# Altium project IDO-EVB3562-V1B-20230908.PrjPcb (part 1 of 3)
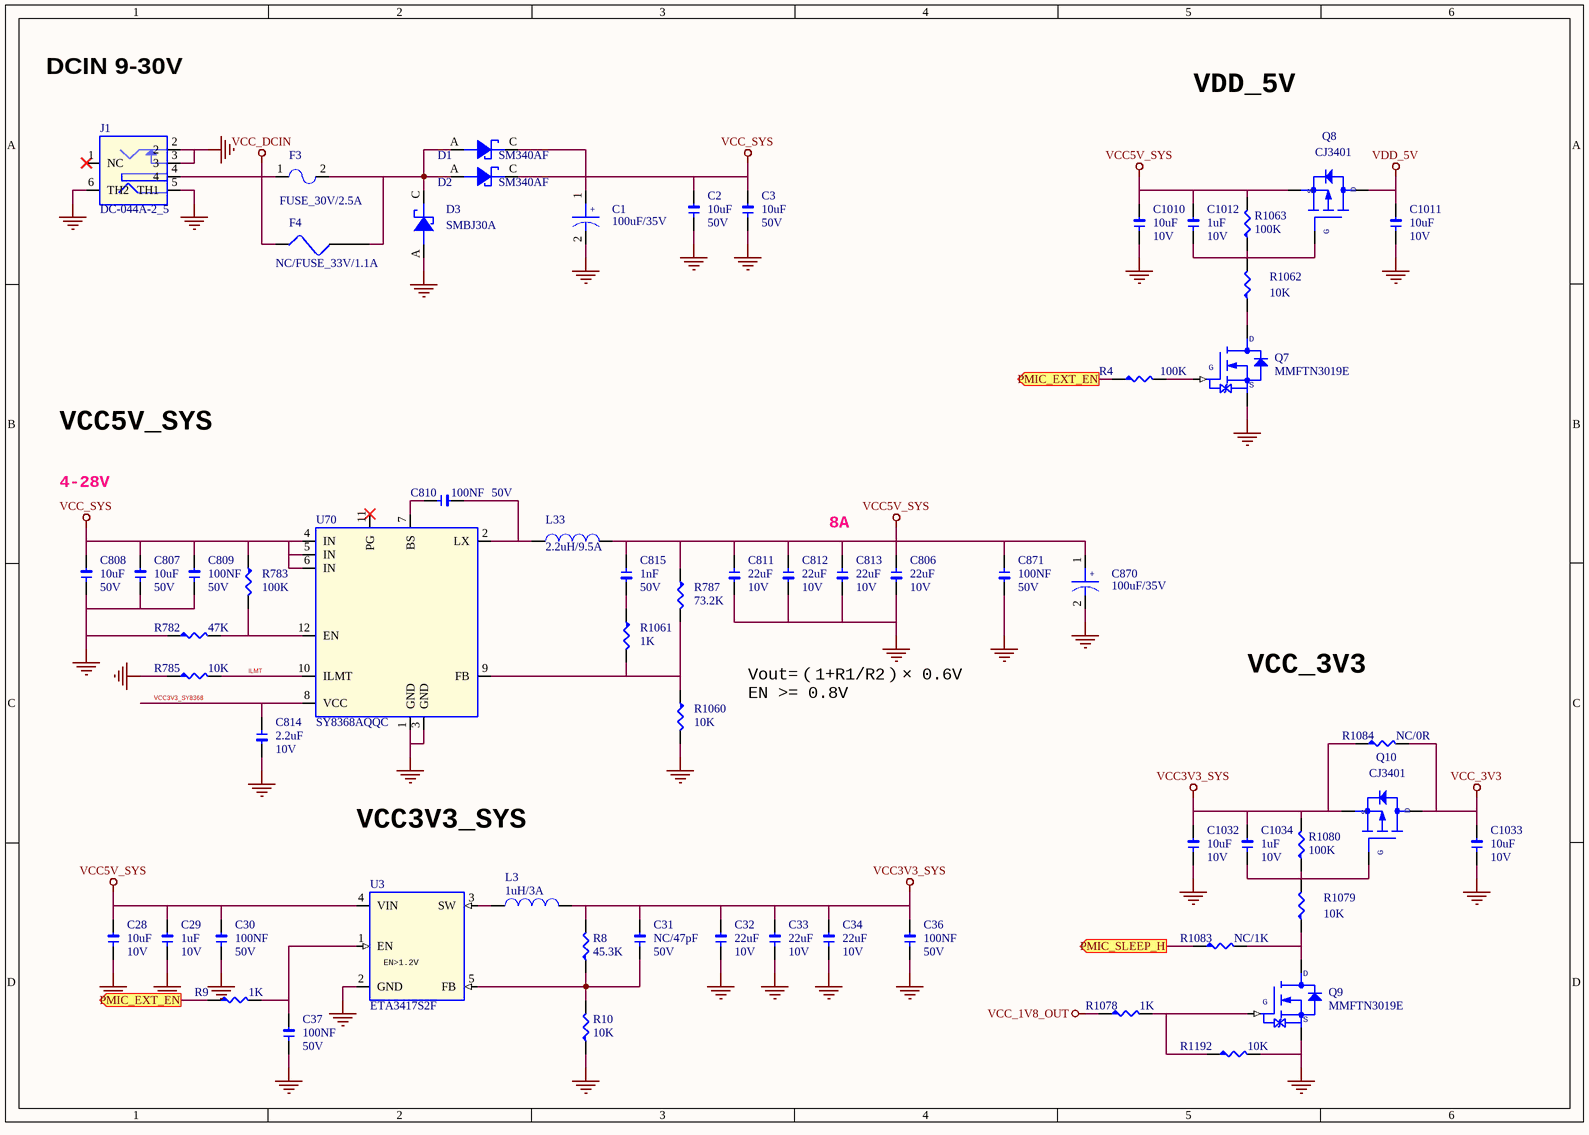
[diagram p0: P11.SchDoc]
14 sheets, 758 parts. Net scope: flat (ports and power ports of the same name join across sheets).
Sheets:
  P11.SchDoc
  P12.SchDoc
  P13.SchDoc
  P14.SchDoc
  P15.SchDoc
  P16.SchDoc
  P17.SchDoc
  P18.SchDoc
  P19.SchDoc
  P20.SchDoc
  P21. USB3.SchDoc
  P22.SchDoc
  P24.SchDoc
  P30.SchDoc

## Sheet P11.SchDoc
size 297 x 209 mm

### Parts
C1  100uF/35V  [CAPAE660X770]
C2  10uF  DSC2: 50V  [1206]
C3  10uF  DSC2: 50V  [1206]
C28  10uF  DSC2: 10V  [1206]
C29  1uF  DSC2: 10V  [1206]
C30  100NF  DSC2: 50V  [1206]
C31  NC/47pF  DSC2: 50V  [1206]
C32  22uF  DSC2: 10V  [1206]
C33  22uF  DSC2: 10V  [1206]
C34  22uF  DSC2: 10V  [1206]
C36  100NF  DSC2: 50V  [1206]
C37  100NF  DSC2: 50V  [1206]
C806  22uF  DSC2: 10V  [1206]
C807  10uF  DSC2: 50V  [1206]
C808  10uF  DSC2: 50V  [1206]
C809  100NF  DSC2: 50V  [1206]
C810  100NF  DSC2: 50V  [1206]
C811  22uF  DSC2: 10V  [1206]
C812  22uF  DSC2: 10V  [1206]
C813  22uF  DSC2: 10V  [1206]
C814  2.2uF  DSC2: 10V  [1206]
C815  1nF  DSC2: 50V  [1206]
C870  100uF/35V  [CAPAE660X770]
C871  100NF  DSC2: 50V  [1206]
C1010  10uF  DSC2: 10V  [1206]
C1011  10uF  DSC2: 10V  [1206]
C1012  1uF  DSC2: 10V  [1206]
C1032  10uF  DSC2: 10V  [1206]
C1033  10uF  DSC2: 10V  [1206]
C1034  1uF  DSC2: 10V  [1206]
D1  SM340AF  [SMAF]
D2  SM340AF  [SMAF]
D3  SMBJ30A  [SMB_DO-214AA]
F3  FUSE_30V/2.5A  [FUSE-DIP-600]
F4  NC/FUSE_33V/1.1A  [SMD1812]
J1  DC-044A-2_5  [DC-044A-2_0-DIP]
L3  1uH/3A  [IND_252012]
L33  2.2uH/9.5A  [IND_73x66]
Q7  MMFTN3019E  [SOT523]
Q8  CJ3401  [SOT23]
Q9  MMFTN3019E  [SOT523]
Q10  CJ3401  [SOT23]
R4  100K  [R0402]
R8  45.3K  [R0402]
R9  1K  [R0402]
R10  10K  [R0402]
R782  47K  [R0402]
R783  100K  [R0402]
R785  10K  [R0402]
R787  73.2K  [R0402]
R1060  10K  [R0402]
R1061  1K  [R0402]
R1062  10K  [R0402]
R1063  100K  [R0402]
R1078  1K  [R0402]
R1079  10K  [R0402]
R1080  100K  [R0402]
R1083  NC/1K  [R0402]
R1084  NC/0R  [R0603]
R1192  10K  [R0402]
U3  ETA3417S2F  [SOT23-5]
U70  SY8368AQQC  [QFN3X3-12-SY8368AQQC]

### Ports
PMIC_EXT_EN (out), PMIC_SLEEP_H (out)

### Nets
GND: C1.2 C2.1 C3.1 C28.1 C29.1 C30.1 C32.1 C33.1 C34.1 C36.1 C37.1 C806.2 C807.1 C808.1 C809.1 C811.2 C812.2 C813.2 C814.2 C870.2 C871.2 C1010.1 C1011.1 C1032.1 C1033.1 D3.A J1.2 J1.3 J1.5(TH1) J1.6(TH2) Q7.2(SOURCE) Q9.2(SOURCE) R10.1 R782.1 R785.1 R1060.2 R1192.2 U3.2(GND) U70.1(GND) U70.3(GND)
VCC3V3_SYS: C31.2 C32.2 C33.2 C34.2 C36.2 C1032.2 C1034.2 L3.2 Q10.2(SOURCE) R8.2 R1080.2 R1084.1
VCC5V_SYS: C28.2 C29.2 C30.2 C806.1 C811.1 C812.1 C813.1 C815.1 C870.1 C871.1 C1010.2 C1012.2 L33.2 Q8.2(SOURCE) R787.1 R1063.2 U3.4(VIN)
VCC_1V8_OUT: R1078.1
VCC_3V3: C1033.2 Q10.3(DRAIN) R1084.2
VCC_DCIN: F3.1 F4.1 J1.4
VCC_SYS: C1.1 C2.2 C3.2 C807.2 C808.2 C809.2 D1.C D2.C R783.1 U70.4(IN) U70.5(IN) U70.6(IN)
VDD_5V: C1011.2 Q8.3(DRAIN)
ILMT: R785.2 U70.10(ILMT)
VCC3V3_SY8368: C814.1 U70.8(VCC)
NetC31_1: C31.1 R8.1 R10.2 U3.5(FB)
NetC37_2: C37.2 R9.2 U3.1(EN)
NetC810_1: C810.1 U70.7(BS)
NetC810_2: C810.2 L33.1 U70.2(LX)
NetC815_2: C815.2 R1061.1
NetC1012_1: C1012.1 Q8.1(GATE) R1062.2 R1063.1
NetC1034_1: C1034.1 Q10.1(GATE) R1079.2 R1080.1
NetD1_A: D1.A D2.A D3.C F3.2 F4.2
NetL3_1: L3.1 U3.3(SW)
NetM1_8: R4.1 R9.1 ; port PMIC_EXT_EN
NetM1_15: R1083.1 ; port PMIC_SLEEP_H
NetQ7_1: Q7.1(GATE) R4.2
NetQ7_3: Q7.3(DRAIN) R1062.1
NetQ9_1: Q9.1(GATE) R1078.2 R1192.1
NetQ9_3: Q9.3(DRAIN) R1079.1 R1083.2
NetR782_2: R782.2 R783.2 U70.12(EN)
NetR787_2: R787.2 R1060.1 R1061.2 U70.9(FB)

Not connected (* = marked no-connect by the designer): J1 1(NC)*; U70 11(PG)*

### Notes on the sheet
- DCIN 9-30V
- VDD_5V
- VCC5V_SYS
- 4-28V
- 8A
- Vout=（1+R1/R2）× 0.6V
  EN >= 0.8V
- VCC_3V3
- VCC3V3_SYS
- (near U3) EN>1.2V

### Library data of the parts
C1 = C-AL-SMD: Manufacture: 先科¦立隆¦三莹; Part Name: 贴片铝电容; Part Number: C020302140007; ID: 7; DSC7: CK1V101M-CRE77(ST); DSC6: SMD,6.3x7.7mm; DSC5: -55~105 ℃; DSC4: 2000H; DSC3: 宽温; DSC2: 35V; DSC1: ±20%
C2 = C-1206: Manufacture: 三星¦国巨¦村田; Part Name: 贴片电容; Part Number: C020103263826; ID: 79; DSC3: X5R; DSC1: ±10%; PCB Footprint: C1206
C3 = C-1206: Part Number: C020103263826; Part Name: 贴片电容; Manufacture: 三星¦国巨¦村田; DSC1: ±10%; DSC3: X5R; ID: 79; PCB Footprint: C1206
C28 C1010 = C-0603: Manufacture: 三星¦国巨¦村田; Part Name: 贴片电容; Part Number: C020102120071; PCB Footprint: C0603; ID: 71; DSC3: X5R; DSC1: ±20%; ERP Number: 1010200076
C29 C1012 = C-0402_Dup1: Part Number: C020102120064; Part Name: 贴片电容; Manufacture: 三星¦国巨¦村田; PCB Footprint: C0402; ERP Number: 1010200054; DSC1: ±10%; DSC3: X5R; ID: 64
C30 C36 C37 C809 C810 = C-0402_Dup2: Part Number: C020102120061; Part Name: 贴片电容; Manufacture: 三星¦国巨¦村田; PCB Footprint: C0402; ERP Number: 1010200128; DSC1: ±10%; DSC3: X7R; ID: 61
C31 = C-0402_Dup1: Part Number: C020102120036; Part Name: 贴片电容; Manufacture: 三星¦国巨¦村田; ERP Number: 1010200213; DSC1: ±5%; DSC3: C0G; ID: 36; PCB Footprint: C0402
C32-C34 = C-0603: Part Number: C020107143899; Part Name: 贴片电容; Manufacture: 三星¦国巨¦村田; DSC1: ±20%; DSC3: X5R; ID: 83; PCB Footprint: C0603
C806 C811-C813 = C-0805: Part Number: C020102120075; Part Name: 贴片电容; Manufacture: 三星¦国巨¦村田; PCB Footprint: C0805; DSC1: ±20%; DSC3: X5R
C807 = C-1206_Dup1: Manufacture: 三星¦国巨¦村田; Part Name: 贴片电容; Part Number: C020103263826; PCB Footprint: C1206; ID: 79; DSC3: X5R; DSC1: ±10%
C808 = C-1206_Dup1: Part Number: C020103263826; Part Name: 贴片电容; Manufacture: 三星¦国巨¦村田; PCB Footprint: C1206; DSC1: ±10%; DSC3: X5R; ID: 79
C814 = C-0402: Manufacture: 三星¦国巨¦村田; Part Name: 贴片电容; Part Number: C020102120066; PCB Footprint: C0402; ID: 66; DSC3: X5R; DSC1: ±10%
C815 = C-0402: Part Number: C020102120054; Part Name: 贴片电容; Manufacture: 三星¦国巨¦村田; PCB Footprint: C0402; ERP Number: 1010200084; DSC1: ±10%; DSC3: X7R; ID: 54
C870 = C-AL-SMD: Part Number: C020302140007; Part Name: 贴片铝电容; Manufacture: 先科¦立隆¦三莹; DSC1: ±20%; DSC2: 35V; DSC3: 宽温; DSC4: 2000H; DSC5: -55~105 ℃; DSC6: SMD,6.3x7.7mm; DSC7: CK1V101M-CRE77(ST); ID: 7
C871 = C-0402_Dup2: Part Number: C020102120061; Part Name: 贴片电容; Manufacture: 三星¦国巨¦村田; ERP Number: 1010200128; DSC1: ±10%; DSC3: X7R; ID: 61; PCB Footprint: C0402
C1011 C1032 C1033 = C-0603: Part Number: C020102120071; Part Name: 贴片电容; Manufacture: 三星¦国巨¦村田; PCB Footprint: C0603; ERP Number: 1010200076; DSC1: ±20%; DSC3: X5R; ID: 71
C1034 = C-0402_Dup1: Manufacture: 三星¦国巨¦村田; Part Name: 贴片电容; Part Number: C020102120064; PCB Footprint: C0402; ID: 64; DSC3: X5R; DSC1: ±10%; ERP Number: 1010200054
D1 = DI-XI-S: Part Number: C040202220007; Part Name: 肖特基二级管; Manufacture: 乐山无线电; CLASS: IC; DSC1: VR=40V; DSC2: IF=3A; DSC3: VF=500mV/3A; ID: 7; Solder: 推荐
D2 = DI-XI-S: Manufacture: 乐山无线电; Part Name: 肖特基二级管; Part Number: C040202220007; CLASS: IC; Solder: 推荐; ID: 7; DSC3: VF=500mV/3A; DSC2: IF=3A; DSC1: VR=40V
D3 = DI-XI-S: Manufacture: 硕凯; Part Name: TVS; CLASS: IC; ID: 32; DSC6: Ppp=600W; DSC3: VBR=33V; DSC2: Vrwm=30V; DSC1: 单向
F3 = FUSE-RL30-300-SIP2: Manufacture: 硕凯; Part Name: 自恢复保险丝; ID: 16; DSC3: SC30-250SW0D; DSC2: 2.5A; DSC1: 30V; PCB Footprint: SIP2-10D-510
F4 = FUSE-SMD1812: Part Name: 自恢复保险丝; Manufacture: 硕凯; DSC1: 33V; DSC2: 1.1A; DSC3: SCF110-33-1812RB; ID: 21
J1 = J-DC-044A-2_5: Part Name: DC座; Part Number: J100103010003; ID: 3; DSC5: DC0044A（九龙熹）; DSC4: DC-044A-2.5A-2.0(星坤); DSC3: 通孔弯针; DSC2: 11.5*10.1*7.3mm; DSC1: 通孔弯针，内径2mm，2.5A，24VDC
L3 = L-IND_Dup1: Manufacture: 宗成¦长江微电¦顺络; Part Name: 功率电感; ID: 52; DSC8: ZCRH252012-1uH-M(宗成); DSC7: FHD252012S-1R0MT(长江微电); DSC6: WPN252012H1R0MT(顺络); DSC5: 2.5*2.0*1.2mm; DSC4: 54mΩ; DSC3: Irms=3A; DSC2: Isat=3.6A; DSC1: ±20%
L33 = L-IND: Part Name: 功率电感; Manufacture: 宗成¦长江微电¦顺络; ERP Number: 1010200471; DSC1: ±20%; DSC2: Isat=9.5A; DSC3: Irms=6.0A; DSC4: 15mΩ; DSC5: 7.3*6.6*3.0mm; DSC6: MWSA0603S-2R2MT(顺络); ID: 37
Q7 Q9 = N-MOS-Q: Manufacture: 先科; Part Name: N-MOS; Part Number: C030202190004; ID: 4; DSC5: pd=150mW; DSC4: Vgs=±20V; DSC3: Vgs(th)=1.5V; DSC2: Id=100mA; DSC1: Vds=30V; ERP Number: 1010800011
Q8 = P-MOS: Manufacture: 长电; Part Number: C030202190001; ID: 1; DSC5: pd=350mW; DSC4: Vgs=±12V; DSC3: Vgs(th)=-1.3V; DSC2: Id=-4.2A; DSC1: Vds=-30V; ERP Number: 1010800001
Q10 = P-MOS: Part Number: C030202190001; Manufacture: 长电; ERP Number: 1010800001; DSC1: Vds=-30V; DSC2: Id=-4.2A; DSC3: Vgs(th)=-1.3V; DSC4: Vgs=±12V; DSC5: pd=350mW; ID: 1
R4 R1080 = R-0402_Dup3: Part Number: C011002080353; Part Name: 贴片电阻; ID: 353; DSC2: 1/16W; DSC1: ±5%; ERP Number: 1010200103
R8 = R-0402_Dup3: Part Name: 贴片电阻; Part Number: C011002080933; DSC1: ±1%; DSC2: 1/16W; ID: 933
R9 R1083 = R-0402_Dup3: Part Name: 贴片电阻; Part Number: C011002080742; ERP Number: 1010200113; DSC1: ±1%; DSC2: 1/16W; ID: 742
R10 R1079 R1192 = R-0402_Dup3: Part Number: C011002080856; Part Name: 贴片电阻; ID: 856; DSC2: 1/16W; DSC1: ±1%; ERP Number: 1010200140
R782 = R-0402_Dup1: Part Name: 贴片电阻; Part Number: C011002080345; ERP Number: 1010200182; DSC1: ±5%; DSC2: 1/16W; ID: 345
R783 = R-0402: Part Number: C011002080353; Part Name: 贴片电阻; ID: 353; DSC2: 1/16W; DSC1: ±5%; ERP Number: 1010200103
R785 = R-0402_Dup1: Part Name: 贴片电阻; Part Number: C011002080328; ERP Number: 1010200096; DSC1: ±5%; DSC2: 1/16W; ID: 328
R787 = R-0402_Dup1: Part Number: C011002080960; Part Name: 贴片电阻; ID: 960; DSC2: 1/16W; DSC1: ±1%; ERP Number: 1010200259
R1060 = R-0402_Dup2: Part Name: 贴片电阻; Part Number: C011002080856; ERP Number: 1010200140; DSC1: ±1%; DSC2: 1/16W; ID: 856
R1061 = R-0402_Dup1: Part Name: 贴片电阻; Part Number: C011002080303; ERP Number: 1010200104; DSC1: ±5%; DSC2: 1/16W; ID: 303
R1062 = R-0402_Dup3: Part Name: 贴片电阻; Part Number: C011002080856; ERP Number: 1010200140; DSC1: ±1%; DSC2: 1/16W; ID: 856
R1063 = R-0402_Dup3: Part Name: 贴片电阻; Part Number: C011002080353; ERP Number: 1010200103; DSC1: ±5%; DSC2: 1/16W; ID: 353
R1078 = R-0402_Dup3: Part Number: C011002080742; Part Name: 贴片电阻; ID: 742; DSC2: 1/16W; DSC1: ±1%; ERP Number: 1010200113
R1084 = R-0603_Dup1: Part Number: C011002081182; Part Name: 贴片电阻; ID: 1,182; DSC2: 1/10W; DSC1: ±1%; ERP Number: 1010200158
U3 = U-ETA3417S2F: Part Name: DCDC; Part Number: C070205183984; Manufacture: ETA; DSC1: Vi=2.6-7.0V; DSC2: Vo=0.6-7.0V; DSC3: Io=2.5A; DSC4: Vfb=0.6V; DSC6: 3MHz; DSC7: 同步降压; DSC8: 替代料：TI的TLV62569DBVR/矽力杰SY8089AAAC; Solder: 量产; ID: 43
U70 = U-SY8368AQQC_6: Part Name: DCDC; Manufacture: 矽力杰; DSC1: Vi=4-28V; DSC2: Vo=0.6~24V; DSC3: I=8A; DSC5: 0.96; DSC6: 800KHz; DSC7: 同步降压; Solder: 推荐; ID: 62

## Sheet P12.SchDoc
size 594 x 420 mm
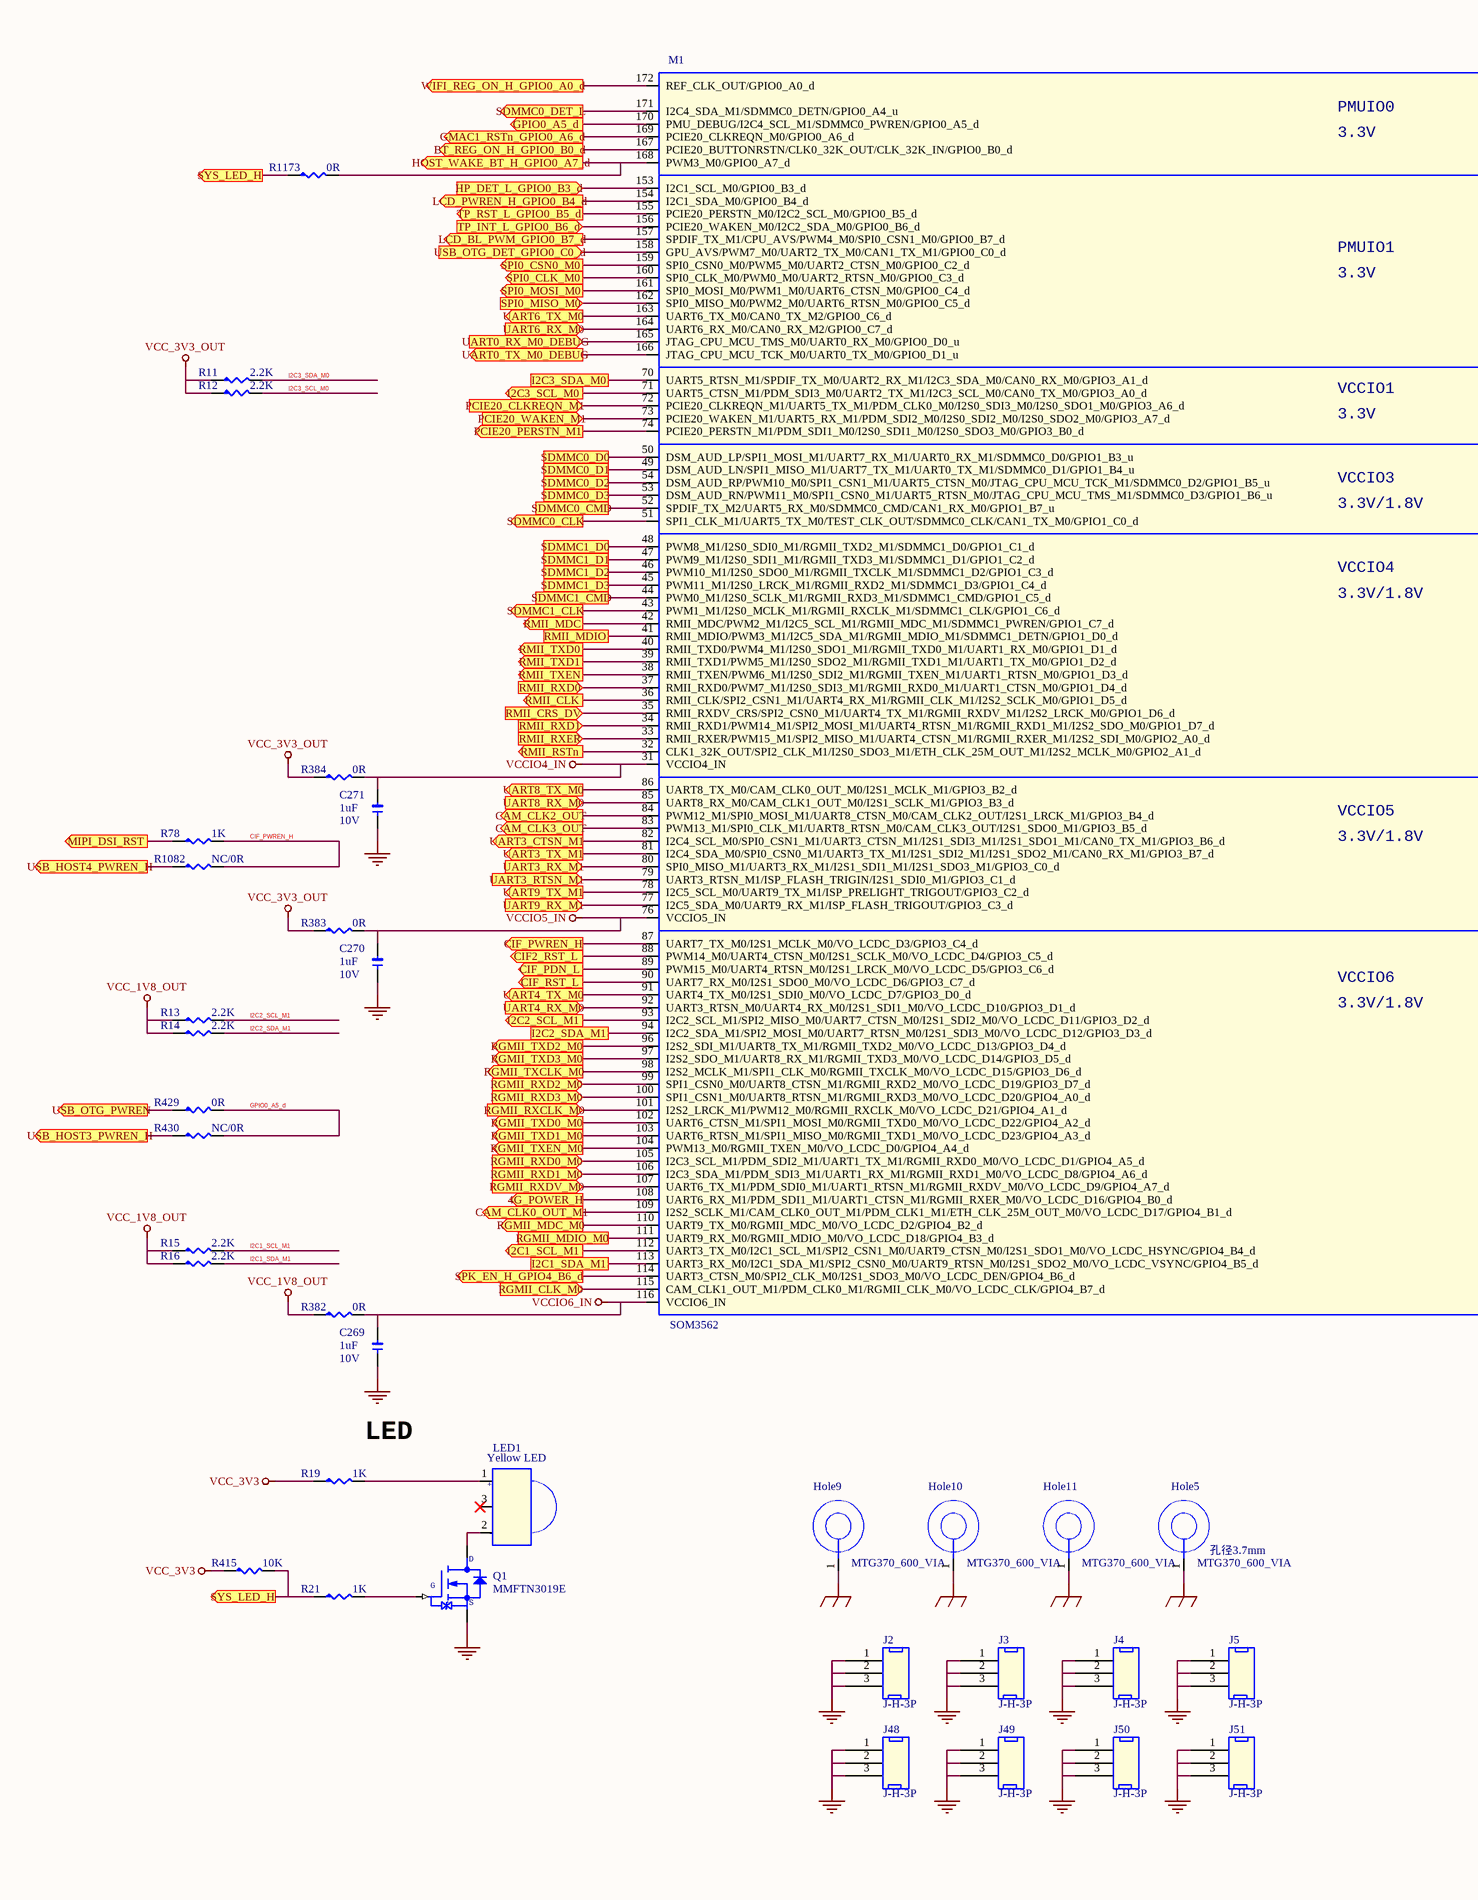
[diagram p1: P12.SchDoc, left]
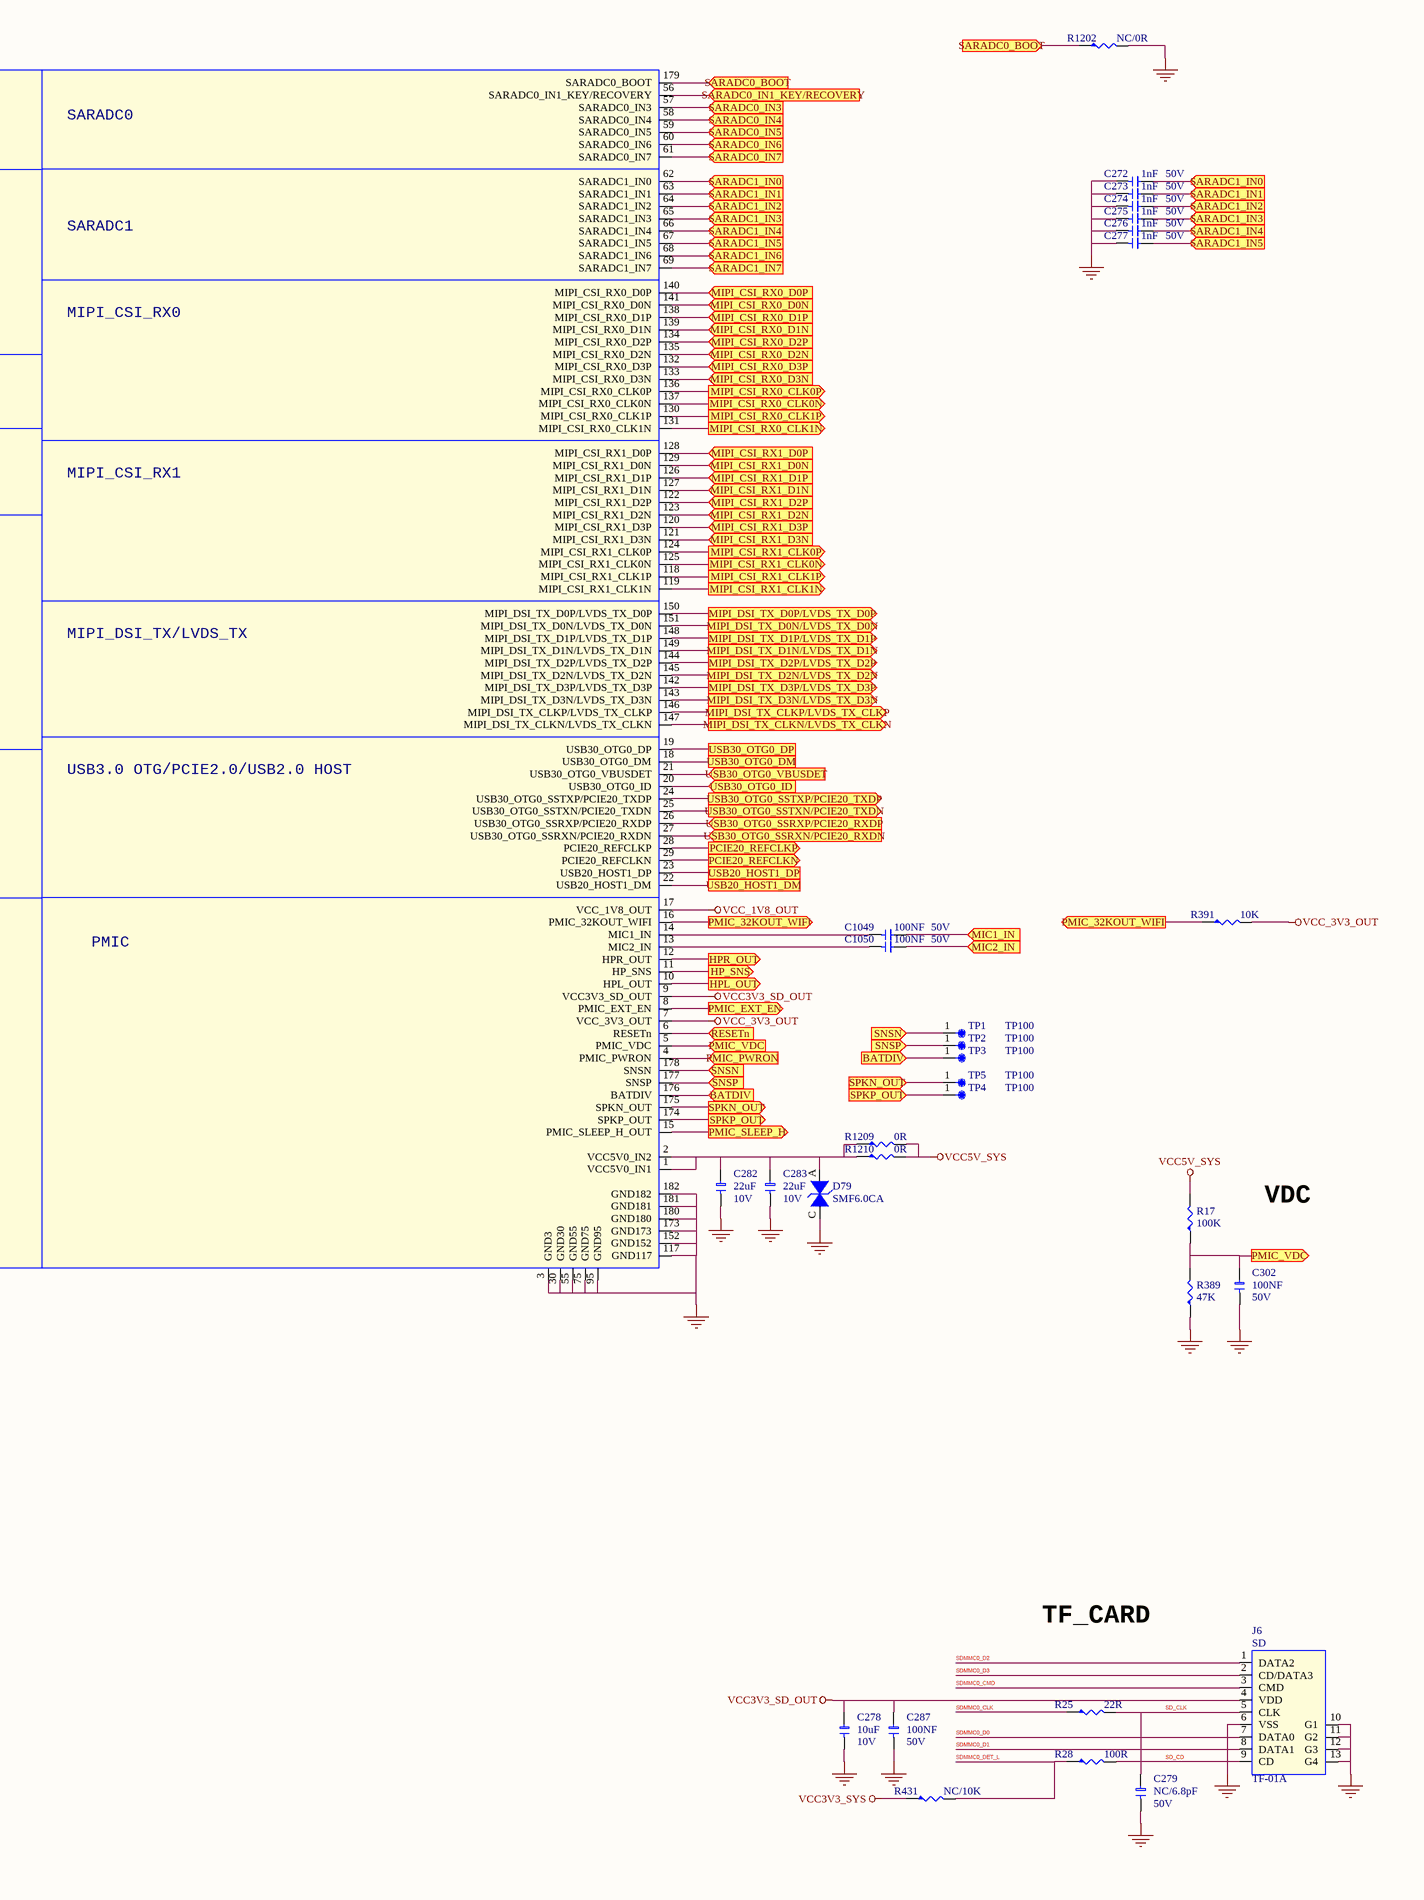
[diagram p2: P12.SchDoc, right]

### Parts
C269  1uF  DSC2: 10V  [1206]
C270  1uF  DSC2: 10V  [1206]
C271  1uF  DSC2: 10V  [1206]
C272  1nF  DSC2: 50V  [1206]
C273  1nF  DSC2: 50V  [1206]
C274  1nF  DSC2: 50V  [1206]
C275  1nF  DSC2: 50V  [1206]
C276  1nF  DSC2: 50V  [1206]
C277  1nF  DSC2: 50V  [1206]
C278  10uF  DSC2: 10V  [1206]
C279  NC/6.8pF  DSC2: 50V  [1206]
C282  22uF  DSC2: 10V  [1206]
C283  22uF  DSC2: 10V  [1206]
C287  100NF  DSC2: 50V  [1206]
C302  100NF  DSC2: 50V  [1206]
C1049  100NF  DSC2: 50V  [1206]
C1050  100NF  DSC2: 50V  [1206]
D79  SMF6.0CA  [SOD-123F]
Hole5  MTG370_600_VIA  DSC2: 孔径3.7mm  [MH276_091]
Hole9  MTG370_600_VIA  [MH276_091]
Hole10  MTG370_600_VIA  [MH276_091]
Hole11  MTG370_600_VIA  [MH276_091]
J2  J-H-3P  [pbz_icsrc6508sfr]
J3  J-H-3P  [pbz_icsrc6508sfr]
J4  J-H-3P  [pbz_icsrc6508sfr]
J5  J-H-3P  [pbz_icsrc6508sfr]
J6  SD  [TF-01A]
J48  J-H-3P  [pbz_icsrc6508sfr]
J49  J-H-3P  [pbz_icsrc6508sfr]
J50  J-H-3P  [pbz_icsrc6508sfr]
J51  J-H-3P  [pbz_icsrc6508sfr]
LED1  Yellow LED  [LED-SMD_3_2X1_5X1_0]
M1  SOM3562  [SOM3562-182P]
Q1  MMFTN3019E  [SOT523]
R11  2.2K  [R0402]
R12  2.2K  [R0402]
R13  2.2K  [R0402]
R14  2.2K  [R0402]
R15  2.2K  [R0402]
R16  2.2K  [R0402]
R17  100K  [R0402]
R19  1K  [R0402]
R21  1K  [R0402]
R25  22R  [R0402]
R28  100R  [R0402]
R78  1K  [R0402]
R382  0R  [R0402]
R383  0R  [R0402]
R384  0R  [R0402]
R389  47K  [R0402]
R391  10K  [R0402]
R415  10K  [R0402]
R429  0R  [R0402]
R430  NC/0R  [R0402]
R431  NC/10K  [R0402]
R1082  NC/0R  [R0402]
R1173  0R  [R0402]
R1202  NC/0R  [R0603]
R1209  0R  [R0603]
R1210  0R  [R0603]
TP1  TP100  [smd_tp_1mm]
TP2  TP100  [smd_tp_1mm]
TP3  TP100  [smd_tp_1mm]
TP4  TP100  [smd_tp_1mm]
TP5  TP100  [smd_tp_1mm]

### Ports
4G_POWER_H (out), BATDIV (in), BT_REG_ON_H_GPIO0_B0_d (out), CAM_CLK0_OUT_M1 (out), CAM_CLK2_OUT (out), CAM_CLK3_OUT (out), CIF2_RST_L (out), CIF_PDN_L (out), CIF_PWREN_H (out), CIF_RST_L (out), GMAC1_RSTn_GPIO0_A6_d (out), GPIO0_A5_d (out), HOST_WAKE_BT_H_GPIO0_A7_d (out), HP_DET_L_GPIO0_B3_d (in), HP_SNS (out), HPL_OUT (out), HPR_OUT (out), I2C1_SCL_M1 (out), I2C1_SDA_M1, I2C2_SCL_M1 (out), I2C2_SDA_M1, I2C3_SCL_M0 (out), I2C3_SDA_M0, LCD_BL_PWM_GPIO0_B7_d (out), LCD_PWREN_H_GPIO0_B4_d (out), MIC1_IN (in), MIC2_IN (in), MIPI_CSI_RX0_CLK0N (out), MIPI_CSI_RX0_CLK0P (out), MIPI_CSI_RX0_CLK1N (out), MIPI_CSI_RX0_CLK1P (out), MIPI_CSI_RX0_D0N (in), MIPI_CSI_RX0_D0P (in), MIPI_CSI_RX0_D1N (in), MIPI_CSI_RX0_D1P (in), MIPI_CSI_RX0_D2N (in), MIPI_CSI_RX0_D2P (in), MIPI_CSI_RX0_D3N (in), MIPI_CSI_RX0_D3P (in), MIPI_CSI_RX1_CLK0N (out), MIPI_CSI_RX1_CLK0P (out), MIPI_CSI_RX1_CLK1N (out), MIPI_CSI_RX1_CLK1P (out), MIPI_CSI_RX1_D0N (in), MIPI_CSI_RX1_D0P (in), MIPI_CSI_RX1_D1N (in), MIPI_CSI_RX1_D1P (in), MIPI_CSI_RX1_D2N (in), MIPI_CSI_RX1_D2P (in), MIPI_CSI_RX1_D3N (in), MIPI_CSI_RX1_D3P (in), MIPI_DSI_RST (out), MIPI_DSI_TX_CLKN/LVDS_TX_CLKN (out), MIPI_DSI_TX_CLKP/LVDS_TX_CLKP (out), MIPI_DSI_TX_D0N/LVDS_TX_D0N (out), MIPI_DSI_TX_D0P/LVDS_TX_D0P (out), MIPI_DSI_TX_D1N/LVDS_TX_D1N (out), MIPI_DSI_TX_D1P/LVDS_TX_D1P (out), MIPI_DSI_TX_D2N/LVDS_TX_D2N (out), MIPI_DSI_TX_D2P/LVDS_TX_D2P (out), MIPI_DSI_TX_D3N/LVDS_TX_D3N (out), MIPI_DSI_TX_D3P/LVDS_TX_D3P (out), PCIE20_CLKREQN_M1 (in), PCIE20_PERSTN_M1 (out), PCIE20_REFCLKN (out), PCIE20_REFCLKP (out), PCIE20_WAKEN_M1 (in), PMIC_32KOUT_WIFI (out), PMIC_EXT_EN (out), PMIC_PWRON (in), PMIC_SLEEP_H (out), PMIC_VDC (in), PMIC_VDC (out), RESETn (in), RGMII_CLK_M0 (in), RGMII_MDC_M0 (out), RGMII_MDIO_M0, RGMII_RXCLK_M0 (in), RGMII_RXD0_M0 (in), RGMII_RXD1_M0 (in), RGMII_RXD2_M0 (in), RGMII_RXD3_M0 (in), RGMII_RXDV_M0 (in), RGMII_TXCLK_M0 (out), RGMII_TXD0_M0 (out), RGMII_TXD1_M0 (out), RGMII_TXD2_M0 (out), RGMII_TXD3_M0 (out), RGMII_TXEN_M0 (out), RMII_CLK (out), RMII_CRS_DV (in), RMII_MDC (out), RMII_MDIO, RMII_RSTn (out), RMII_RXD0 (in), RMII_RXD1 (in), RMII_RXER (in), RMII_TXD0 (out), RMII_TXD1 (out), RMII_TXEN (out), SARADC0_BOOT (in), SARADC0_IN1_KEY/RECOVERY (in), SARADC0_IN3 (in), SARADC0_IN4 (in), SARADC0_IN5 (in), SARADC0_IN6 (in), SARADC0_IN7 (in), SARADC1_IN0 (in), SARADC1_IN1 (in), SARADC1_IN2 (in), SARADC1_IN3 (in), SARADC1_IN4 (in), SARADC1_IN5 (in), SARADC1_IN6 (in), SARADC1_IN7 (in), SDMMC0_CLK (out), SDMMC0_CMD, SDMMC0_D0, SDMMC0_D1, SDMMC0_D2, SDMMC0_D3, SDMMC0_DET_L (out), SDMMC1_CLK (out), SDMMC1_CMD, SDMMC1_D0, SDMMC1_D1, SDMMC1_D2, SDMMC1_D3, SNSN (in), SNSP (in), SPI0_CLK_M0 (out), SPI0_CSN0_M0 (out), SPI0_MISO_M0 (in), SPI0_MOSI_M0 (out), SPK_EN_H_GPIO4_B6_d (out), SPKN_OUT (in), SPKN_OUT (out), SPKP_OUT (in), SPKP_OUT (out), SYS_LED_H (out), TP_INT_L_GPIO0_B6_d (in), TP_RST_L_GPIO0_B5_d (out), UART0_RX_M0_DEBUG (in), UART0_TX_M0_DEBUG (out), UART3_CTSN_M1 (out), UART3_RTSN_M1 (in), UART3_RX_M1 (in), UART3_TX_M1 (out), UART4_RX_M0 (in), UART4_TX_M0 (out), UART6_RX_M0 (in), UART6_TX_M0 (out), UART8_RX_M0 (in), UART8_TX_M0 (out), UART9_RX_M1 (in), UART9_TX_M1 (out), USB20_HOST1_DM, USB20_HOST1_DP, USB30_OTG0_DM, USB30_OTG0_DP, USB30_OTG0_ID (in), USB30_OTG0_SSRXN/PCIE20_RXDN (in), USB30_OTG0_SSRXP/PCIE20_RXDP (in), USB30_OTG0_SSTXN/PCIE20_TXDN (out), USB30_OTG0_SSTXP/PCIE20_TXDP (out), USB30_OTG0_VBUSDET (in), USB_HOST3_PWREN_H (out), USB_HOST4_PWREN_H (out), USB_OTG_DET_GPIO0_C0_d (in), USB_OTG_PWREN (out), WIFI_REG_ON_H_GPIO0_A0_d (out)

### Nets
GND: C269.1 C270.1 C271.1 C272.1 C273.1 C274.1 C275.1 C276.1 C277.1 C278.1 C279.1 C282.1 C283.1 C287.1 C302.1 D79.C(I/O1) J2.1 J2.2 J2.3 J3.1 J3.2 J3.3 J4.1 J4.2 J4.3 J5.1 J5.2 J5.3 J6.6(VSS) J6.10(G1) J6.11(G2) J6.12(G3) J6.13(G4) J48.1 J48.2 J48.3 J49.1 J49.2 J49.3 J50.1 J50.2 J50.3 J51.1 J51.2 J51.3 M1.3(GND3) M1.30(GND30) M1.55(GND55) M1.75(GND75) M1.95(GND95) M1.117(GND117) M1.152(GND152) M1.173(GND173) M1.180(GND180) M1.181(GND181) M1.182(GND182) Q1.2(SOURCE) R389.1 R1202.2
GND_EARTH: Hole5.1 Hole9.1 Hole10.1 Hole11.1
VCC3V3_SD_OUT: C278.2 C287.2 J6.4(VDD) M1.9(VCC3V3_SD_OUT)
VCC3V3_SYS: R431.1
VCC5V_SYS: R17.2 R1209.2 R1210.2
VCC_1V8_OUT: M1.17(VCC_1V8_OUT) R13.1 R14.1 R15.1 R16.1 R382.1
VCC_3V3: R19.1 R415.1
VCC_3V3_OUT: M1.7(VCC_3V3_OUT) R11.1 R12.1 R383.1 R384.1 R391.2
VCCIO4_IN: C271.2 M1.31(VCCIO4_IN) R384.2
VCCIO5_IN: C270.2 M1.76(VCCIO5_IN) R383.2
VCCIO6_IN: C269.2 M1.116(VCCIO6_IN) R382.2
4G_POWER_H: M1.108(UART6_RX_M1/PDM_SDI1_M1/UART1_CTSN_M1/RGMII_RXER_M0/VO_LCDC_D16/GPIO4_B0_d) ; port 4G_POWER_H
CIF_PWREN_H: R78.2 R1082.2
GPIO0_A5_d: R429.2 R430.2
HP_DET_L: M1.153(I2C1_SCL_M0/GPIO0_B3_d) ; port HP_DET_L_GPIO0_B3_d
HUB_HOST3_PWREN_H: R430.1 ; port USB_HOST3_PWREN_H
HUB_HOST4_PWREN_H: R1082.1 ; port USB_HOST4_PWREN_H
I2C1_SCL_M1: R15.2
I2C1_SDA_M1: R16.2
I2C2_SCL_M1: R13.2
I2C2_SDA_M1: R14.2
I2C3_SCL_M0: R12.2
I2C3_SDA_M0: R11.2
LCD_TX_CLKN: M1.147(MIPI_DSI_TX_CLKN/LVDS_TX_CLKN) ; port MIPI_DSI_TX_CLKN/LVDS_TX_CLKN
LCD_TX_CLKP: M1.146(MIPI_DSI_TX_CLKP/LVDS_TX_CLKP) ; port MIPI_DSI_TX_CLKP/LVDS_TX_CLKP
LCD_TX_D0N: M1.151(MIPI_DSI_TX_D0N/LVDS_TX_D0N) ; port MIPI_DSI_TX_D0N/LVDS_TX_D0N
LCD_TX_D0P: M1.150(MIPI_DSI_TX_D0P/LVDS_TX_D0P) ; port MIPI_DSI_TX_D0P/LVDS_TX_D0P
LCD_TX_D1N: M1.149(MIPI_DSI_TX_D1N/LVDS_TX_D1N) ; port MIPI_DSI_TX_D1N/LVDS_TX_D1N
LCD_TX_D1P: M1.148(MIPI_DSI_TX_D1P/LVDS_TX_D1P) ; port MIPI_DSI_TX_D1P/LVDS_TX_D1P
LCD_TX_D2N: M1.145(MIPI_DSI_TX_D2N/LVDS_TX_D2N) ; port MIPI_DSI_TX_D2N/LVDS_TX_D2N
LCD_TX_D2P: M1.144(MIPI_DSI_TX_D2P/LVDS_TX_D2P) ; port MIPI_DSI_TX_D2P/LVDS_TX_D2P
LCD_TX_D3N: M1.143(MIPI_DSI_TX_D3N/LVDS_TX_D3N) ; port MIPI_DSI_TX_D3N/LVDS_TX_D3N
LCD_TX_D3P: M1.142(MIPI_DSI_TX_D3P/LVDS_TX_D3P) ; port MIPI_DSI_TX_D3P/LVDS_TX_D3P
MIPI_RST: R78.1 ; port MIPI_DSI_RST
RMII_RXD0: M1.37(RMII_RXD0/PWM7_M1/I2S0_SDI3_M1/RGMII_RXD0_M1/UART1_CTSN_M0/GPIO1_D4_d) ; port RMII_RXD0
RMII_RXD1: M1.34(RMII_RXD1/PWM14_M1/SPI2_MOSI_M1/UART4_RTSN_M1/RGMII_RXD1_M1/I2S2_SDO_M0/GPIO1_D7_d) ; port RMII_RXD1
RMII_RXDV: M1.35(RMII_RXDV_CRS/SPI2_CSN0_M1/UART4_TX_M1/RGMII_RXDV_M1/I2S2_LRCK_M0/GPIO1_D6_d) ; port RMII_CRS_DV
SCL_TP: M1.71(UART5_CTSN_M1/PDM_SDI3_M0/UART2_TX_M1/I2C3_SCL_M0/CAN0_TX_M0/GPIO3_A0_d) ; port I2C3_SCL_M0
SD_CD: J6.9(CD) R28.2
SD_CLK: C279.2 J6.5(CLK) R25.2
SDA_TP: M1.70(UART5_RTSN_M1/SPDIF_TX_M0/UART2_RX_M1/I2C3_SDA_M0/CAN0_RX_M0/GPIO3_A1_d) ; port I2C3_SDA_M0
SDMMC0_CLK: R25.1
SDMMC0_CMD: J6.3(CMD)
SDMMC0_D0: J6.7(DATA0)
SDMMC0_D1: J6.8(DATA1)
SDMMC0_D2: J6.1(DATA2)
SDMMC0_D3: J6.2(CD/DATA3)
SDMMC0_DET_L: R28.1 R431.2
SPK_CTL_H: M1.114(UART3_CTSN_M0/SPI2_CLK_M0/I2S1_SDO3_M0/VO_LCDC_DEN/GPIO4_B6_d) ; port SPK_EN_H_GPIO4_B6_d
TP_INT_L: M1.156(PCIE20_WAKEN_M0/I2C2_SDA_M0/GPIO0_B6_d) ; port TP_INT_L_GPIO0_B6_d
TP_RST_L: M1.155(PCIE20_PERSTN_M0/I2C2_SCL_M0/GPIO0_B5_d) ; port TP_RST_L_GPIO0_B5_d
NetC155_2: M1.36(RMII_CLK/SPI2_CSN1_M1/UART4_RX_M1/RGMII_CLK_M1/I2S2_SCLK_M0/GPIO1_D5_d) ; port RMII_CLK
NetC272_2: C272.2 M1.62(SARADC1_IN0) ; port SARADC1_IN0
NetC273_2: C273.2 M1.63(SARADC1_IN1) ; port SARADC1_IN1
NetC274_2: C274.2 M1.64(SARADC1_IN2) ; port SARADC1_IN2
NetC275_2: C275.2 M1.65(SARADC1_IN3) ; port SARADC1_IN3
NetC276_2: C276.2 M1.66(SARADC1_IN4) ; port SARADC1_IN4
NetC277_2: C277.2 M1.67(SARADC1_IN5) ; port SARADC1_IN5
NetC282_2: C282.2 C283.2 D79.A(I/O2) M1.1(VCC5V0_IN1) M1.2(VCC5V0_IN2) R1209.1 R1210.1
NetC302_2: C302.2 M1.5(PMIC_VDC) R17.1 R389.2 ; port PMIC_VDC
NetC1049_1: C1049.1 M1.14(MIC1_IN)
NetC1049_2: C1049.2 ; port MIC1_IN
NetC1050_1: C1050.1 M1.13(MIC2_IN)
NetC1050_2: C1050.2 ; port MIC2_IN
NetLED1_1: LED1.1(+) R19.2
NetLED1_2: LED1.2(-) Q1.3(DRAIN)
NetM1_4: M1.4(PMIC_PWRON) ; port PMIC_PWRON
NetM1_6: M1.6(RESETn) ; port RESETn
NetM1_8: M1.8(PMIC_EXT_EN) ; port PMIC_EXT_EN
NetM1_10: M1.10(HPL_OUT) ; port HPL_OUT
NetM1_11: M1.11(HP_SNS) ; port HP_SNS
NetM1_12: M1.12(HPR_OUT) ; port HPR_OUT
NetM1_15: M1.15(PMIC_SLEEP_H_OUT) ; port PMIC_SLEEP_H
NetM1_16: M1.16(PMIC_32KOUT_WIFI) R391.1 ; port PMIC_32KOUT_WIFI
NetM1_18: M1.18(USB30_OTG0_DM) ; port USB30_OTG0_DM
NetM1_19: M1.19(USB30_OTG0_DP) ; port USB30_OTG0_DP
NetM1_20: M1.20(USB30_OTG0_ID) ; port USB30_OTG0_ID
NetM1_21: M1.21(USB30_OTG0_VBUSDET) ; port USB30_OTG0_VBUSDET
NetM1_22: M1.22(USB20_HOST1_DM) ; port USB20_HOST1_DM
NetM1_23: M1.23(USB20_HOST1_DP) ; port USB20_HOST1_DP
NetM1_24: M1.24(USB30_OTG0_SSTXP/PCIE20_TXDP) ; port USB30_OTG0_SSTXP/PCIE20_TXDP
NetM1_25: M1.25(USB30_OTG0_SSTXN/PCIE20_TXDN) ; port USB30_OTG0_SSTXN/PCIE20_TXDN
NetM1_26: M1.26(USB30_OTG0_SSRXP/PCIE20_RXDP) ; port USB30_OTG0_SSRXP/PCIE20_RXDP
NetM1_27: M1.27(USB30_OTG0_SSRXN/PCIE20_RXDN) ; port USB30_OTG0_SSRXN/PCIE20_RXDN
NetM1_28: M1.28(PCIE20_REFCLKP) ; port PCIE20_REFCLKP
NetM1_29: M1.29(PCIE20_REFCLKN) ; port PCIE20_REFCLKN
NetM1_32: M1.32(CLK1_32K_OUT/SPI2_CLK_M1/I2S0_SDO3_M1/ETH_CLK_25M_OUT_M1/I2S2_MCLK_M0/GPIO2_A1_d) ; port RMII_RSTn
NetM1_33: M1.33(RMII_RXER/PWM15_M1/SPI2_MISO_M1/UART4_CTSN_M1/RGMII_RXER_M1/I2S2_SDI_M0/GPIO2_A0_d) ; port RMII_RXER
NetM1_38: M1.38(RMII_TXEN/PWM6_M1/I2S0_SDI2_M1/RGMII_TXEN_M1/UART1_RTSN_M0/GPIO1_D3_d) ; port RMII_TXEN
NetM1_39: M1.39(RMII_TXD1/PWM5_M1/I2S0_SDO2_M1/RGMII_TXD1_M1/UART1_TX_M0/GPIO1_D2_d) ; port RMII_TXD1
NetM1_40: M1.40(RMII_TXD0/PWM4_M1/I2S0_SDO1_M1/RGMII_TXD0_M1/UART1_RX_M0/GPIO1_D1_d) ; port RMII_TXD0
NetM1_41: M1.41(RMII_MDIO/PWM3_M1/I2C5_SDA_M1/RGMII_MDIO_M1/SDMMC1_DETN/GPIO1_D0_d) ; port RMII_MDIO
NetM1_42: M1.42(RMII_MDC/PWM2_M1/I2C5_SCL_M1/RGMII_MDC_M1/SDMMC1_PWREN/GPIO1_C7_d) ; port RMII_MDC
NetM1_43: M1.43(PWM1_M1/I2S0_MCLK_M1/RGMII_RXCLK_M1/SDMMC1_CLK/GPIO1_C6_d) ; port SDMMC1_CLK
NetM1_44: M1.44(PWM0_M1/I2S0_SCLK_M1/RGMII_RXD3_M1/SDMMC1_CMD/GPIO1_C5_d) ; port SDMMC1_CMD
NetM1_45: M1.45(PWM11_M1/I2S0_LRCK_M1/RGMII_RXD2_M1/SDMMC1_D3/GPIO1_C4_d) ; port SDMMC1_D3
NetM1_46: M1.46(PWM10_M1/I2S0_SDO0_M1/RGMII_TXCLK_M1/SDMMC1_D2/GPIO1_C3_d) ; port SDMMC1_D2
NetM1_47: M1.47(PWM9_M1/I2S0_SDI1_M1/RGMII_TXD3_M1/SDMMC1_D1/GPIO1_C2_d) ; port SDMMC1_D1
NetM1_48: M1.48(PWM8_M1/I2S0_SDI0_M1/RGMII_TXD2_M1/SDMMC1_D0/GPIO1_C1_d) ; port SDMMC1_D0
NetM1_49: M1.49(DSM_AUD_LN/SPI1_MISO_M1/UART7_TX_M1/UART0_TX_M1/SDMMC0_D1/GPIO1_B4_u) ; port SDMMC0_D1
NetM1_50: M1.50(DSM_AUD_LP/SPI1_MOSI_M1/UART7_RX_M1/UART0_RX_M1/SDMMC0_D0/GPIO1_B3_u) ; port SDMMC0_D0
NetM1_51: M1.51(SPI1_CLK_M1/UART5_TX_M0/TEST_CLK_OUT/SDMMC0_CLK/CAN1_TX_M0/GPIO1_C0_d) ; port SDMMC0_CLK
NetM1_52: M1.52(SPDIF_TX_M2/UART5_RX_M0/SDMMC0_CMD/CAN1_RX_M0/GPIO1_B7_u) ; port SDMMC0_CMD
NetM1_53: M1.53(DSM_AUD_RN/PWM11_M0/SPI1_CSN0_M1/UART5_RTSN_M0/JTAG_CPU_MCU_TMS_M1/SDMMC0_D3/GPIO1_B6_u) ; port SDMMC0_D3
NetM1_54: M1.54(DSM_AUD_RP/PWM10_M0/SPI1_CSN1_M1/UART5_CTSN_M0/JTAG_CPU_MCU_TCK_M1/SDMMC0_D2/GPIO1_B5_u) ; port SDMMC0_D2
NetM1_56: M1.56(SARADC0_IN1_KEY/RECOVERY) ; port SARADC0_IN1_KEY/RECOVERY
NetM1_57: M1.57(SARADC0_IN3) ; port SARADC0_IN3
NetM1_58: M1.58(SARADC0_IN4) ; port SARADC0_IN4
NetM1_59: M1.59(SARADC0_IN5) ; port SARADC0_IN5
NetM1_60: M1.60(SARADC0_IN6) ; port SARADC0_IN6
NetM1_61: M1.61(SARADC0_IN7) ; port SARADC0_IN7
NetM1_68: M1.68(SARADC1_IN6) ; port SARADC1_IN6
NetM1_69: M1.69(SARADC1_IN7) ; port SARADC1_IN7
NetM1_72: M1.72(PCIE20_CLKREQN_M1/UART5_TX_M1/PDM_CLK0_M0/I2S0_SDI3_M0/I2S0_SDO1_M0/GPIO3_A6_d) ; port PCIE20_CLKREQN_M1
NetM1_73: M1.73(PCIE20_WAKEN_M1/UART5_RX_M1/PDM_SDI2_M0/I2S0_SDI2_M0/I2S0_SDO2_M0/GPIO3_A7_d) ; port PCIE20_WAKEN_M1
NetM1_74: M1.74(PCIE20_PERSTN_M1/PDM_SDI1_M0/I2S0_SDI1_M0/I2S0_SDO3_M0/GPIO3_B0_d) ; port PCIE20_PERSTN_M1
NetM1_77: M1.77(I2C5_SDA_M0/UART9_RX_M1/ISP_FLASH_TRIGOUT/GPIO3_C3_d) ; port UART9_RX_M1
NetM1_78: M1.78(I2C5_SCL_M0/UART9_TX_M1/ISP_PRELIGHT_TRIGOUT/GPIO3_C2_d) ; port UART9_TX_M1
NetM1_79: M1.79(UART3_RTSN_M1/ISP_FLASH_TRIGIN/I2S1_SDI0_M1/GPIO3_C1_d) ; port UART3_RTSN_M1
NetM1_80: M1.80(SPI0_MISO_M1/UART3_RX_M1/I2S1_SDI1_M1/I2S1_SDO3_M1/GPIO3_C0_d) ; port UART3_RX_M1
NetM1_81: M1.81(I2C4_SDA_M0/SPI0_CSN0_M1/UART3_TX_M1/I2S1_SDI2_M1/I2S1_SDO2_M1/CAN0_RX_M1/GPIO3_B7_d) ; port UART3_TX_M1
NetM1_82: M1.82(I2C4_SCL_M0/SPI0_CSN1_M1/UART3_CTSN_M1/I2S1_SDI3_M1/I2S1_SDO1_M1/CAN0_TX_M1/GPIO3_B6_d) ; port UART3_CTSN_M1
NetM1_83: M1.83(PWM13_M1/SPI0_CLK_M1/UART8_RTSN_M0/CAM_CLK3_OUT/I2S1_SDO0_M1/GPIO3_B5_d) ; port CAM_CLK3_OUT
NetM1_84: M1.84(PWM12_M1/SPI0_MOSI_M1/UART8_CTSN_M0/CAM_CLK2_OUT/I2S1_LRCK_M1/GPIO3_B4_d) ; port CAM_CLK2_OUT
NetM1_85: M1.85(UART8_RX_M0/CAM_CLK1_OUT_M0/I2S1_SCLK_M1/GPIO3_B3_d) ; port UART8_RX_M0
NetM1_86: M1.86(UART8_TX_M0/CAM_CLK0_OUT_M0/I2S1_MCLK_M1/GPIO3_B2_d) ; port UART8_TX_M0
NetM1_87: M1.87(UART7_TX_M0/I2S1_MCLK_M0/VO_LCDC_D3/GPIO3_C4_d) ; port CIF_PWREN_H
NetM1_88: M1.88(PWM14_M0/UART4_CTSN_M0/I2S1_SCLK_M0/VO_LCDC_D4/GPIO3_C5_d) ; port CIF2_RST_L
NetM1_89: M1.89(PWM15_M0/UART4_RTSN_M0/I2S1_LRCK_M0/VO_LCDC_D5/GPIO3_C6_d) ; port CIF_PDN_L
NetM1_90: M1.90(UART7_RX_M0/I2S1_SDO0_M0/VO_LCDC_D6/GPIO3_C7_d) ; port CIF_RST_L
NetM1_91: M1.91(UART4_TX_M0/I2S1_SDI0_M0/VO_LCDC_D7/GPIO3_D0_d) ; port UART4_TX_M0
NetM1_92: M1.92(UART3_RTSN_M0/UART4_RX_M0/I2S1_SDI1_M0/VO_LCDC_D10/GPIO3_D1_d) ; port UART4_RX_M0
NetM1_93: M1.93(I2C2_SCL_M1/SPI2_MISO_M0/UART7_CTSN_M0/I2S1_SDI2_M0/VO_LCDC_D11/GPIO3_D2_d) ; port I2C2_SCL_M1
NetM1_94: M1.94(I2C2_SDA_M1/SPI2_MOSI_M0/UART7_RTSN_M0/I2S1_SDI3_M0/VO_LCDC_D12/GPIO3_D3_d) ; port I2C2_SDA_M1
NetM1_96: M1.96(I2S2_SDI_M1/UART8_TX_M1/RGMII_TXD2_M0/VO_LCDC_D13/GPIO3_D4_d) ; port RGMII_TXD2_M0
NetM1_97: M1.97(I2S2_SDO_M1/UART8_RX_M1/RGMII_TXD3_M0/VO_LCDC_D14/GPIO3_D5_d) ; port RGMII_TXD3_M0
NetM1_98: M1.98(I2S2_MCLK_M1/SPI1_CLK_M0/RGMII_TXCLK_M0/VO_LCDC_D15/GPIO3_D6_d) ; port RGMII_TXCLK_M0
NetM1_99: M1.99(SPI1_CSN0_M0/UART8_CTSN_M1/RGMII_RXD2_M0/VO_LCDC_D19/GPIO3_D7_d) ; port RGMII_RXD2_M0
NetM1_100: M1.100(SPI1_CSN1_M0/UART8_RTSN_M1/RGMII_RXD3_M0/VO_LCDC_D20/GPIO4_A0_d) ; port RGMII_RXD3_M0
NetM1_101: M1.101(I2S2_LRCK_M1/PWM12_M0/RGMII_RXCLK_M0/VO_LCDC_D21/GPIO4_A1_d) ; port RGMII_RXCLK_M0
NetM1_102: M1.102(UART6_CTSN_M1/SPI1_MOSI_M0/RGMII_TXD0_M0/VO_LCDC_D22/GPIO4_A2_d) ; port RGMII_TXD0_M0
NetM1_103: M1.103(UART6_RTSN_M1/SPI1_MISO_M0/RGMII_TXD1_M0/VO_LCDC_D23/GPIO4_A3_d) ; port RGMII_TXD1_M0
NetM1_104: M1.104(PWM13_M0/RGMII_TXEN_M0/VO_LCDC_D0/GPIO4_A4_d) ; port RGMII_TXEN_M0
NetM1_105: M1.105(I2C3_SCL_M1/PDM_SDI2_M1/UART1_TX_M1/RGMII_RXD0_M0/VO_LCDC_D1/GPIO4_A5_d) ; port RGMII_RXD0_M0
NetM1_106: M1.106(I2C3_SDA_M1/PDM_SDI3_M1/UART1_RX_M1/RGMII_RXD1_M0/VO_LCDC_D8/GPIO4_A6_d) ; port RGMII_RXD1_M0
NetM1_107: M1.107(UART6_TX_M1/PDM_SDI0_M1/UART1_RTSN_M1/RGMII_RXDV_M0/VO_LCDC_D9/GPIO4_A7_d) ; port RGMII_RXDV_M0
NetM1_109: M1.109(I2S2_SCLK_M1/CAM_CLK0_OUT_M1/PDM_CLK1_M1/ETH_CLK_25M_OUT_M0/VO_LCDC_D17/GPIO4_B1_d) ; port CAM_CLK0_OUT_M1
NetM1_110: M1.110(UART9_TX_M0/RGMII_MDC_M0/VO_LCDC_D2/GPIO4_B2_d) ; port RGMII_MDC_M0
NetM1_111: M1.111(UART9_RX_M0/RGMII_MDIO_M0/VO_LCDC_D18/GPIO4_B3_d) ; port RGMII_MDIO_M0
NetM1_112: M1.112(UART3_TX_M0/I2C1_SCL_M1/SPI2_CSN1_M0/UART9_CTSN_M0/I2S1_SDO1_M0/VO_LCDC_HSYNC/GPIO4_B4_d) ; port I2C1_SCL_M1
NetM1_113: M1.113(UART3_RX_M0/I2C1_SDA_M1/SPI2_CSN0_M0/UART9_RTSN_M0/I2S1_SDO2_M0/VO_LCDC_VSYNC/GPIO4_B5_d) ; port I2C1_SDA_M1
NetM1_115: M1.115(CAM_CLK1_OUT_M1/PDM_CLK0_M1/RGMII_CLK_M0/VO_LCDC_CLK/GPIO4_B7_d) ; port RGMII_CLK_M0
NetM1_118: M1.118(MIPI_CSI_RX1_CLK1P) ; port MIPI_CSI_RX1_CLK1P
NetM1_119: M1.119(MIPI_CSI_RX1_CLK1N) ; port MIPI_CSI_RX1_CLK1N
NetM1_120: M1.120(MIPI_CSI_RX1_D3P) ; port MIPI_CSI_RX1_D3P
NetM1_121: M1.121(MIPI_CSI_RX1_D3N) ; port MIPI_CSI_RX1_D3N
NetM1_122: M1.122(MIPI_CSI_RX1_D2P) ; port MIPI_CSI_RX1_D2P
NetM1_123: M1.123(MIPI_CSI_RX1_D2N) ; port MIPI_CSI_RX1_D2N
NetM1_124: M1.124(MIPI_CSI_RX1_CLK0P) ; port MIPI_CSI_RX1_CLK0P
NetM1_125: M1.125(MIPI_CSI_RX1_CLK0N) ; port MIPI_CSI_RX1_CLK0N
NetM1_126: M1.126(MIPI_CSI_RX1_D1P) ; port MIPI_CSI_RX1_D1P
NetM1_127: M1.127(MIPI_CSI_RX1_D1N) ; port MIPI_CSI_RX1_D1N
NetM1_128: M1.128(MIPI_CSI_RX1_D0P) ; port MIPI_CSI_RX1_D0P
NetM1_129: M1.129(MIPI_CSI_RX1_D0N) ; port MIPI_CSI_RX1_D0N
NetM1_130: M1.130(MIPI_CSI_RX0_CLK1P) ; port MIPI_CSI_RX0_CLK1P
NetM1_131: M1.131(MIPI_CSI_RX0_CLK1N) ; port MIPI_CSI_RX0_CLK1N
NetM1_132: M1.132(MIPI_CSI_RX0_D3P) ; port MIPI_CSI_RX0_D3P
NetM1_133: M1.133(MIPI_CSI_RX0_D3N) ; port MIPI_CSI_RX0_D3N
NetM1_134: M1.134(MIPI_CSI_RX0_D2P) ; port MIPI_CSI_RX0_D2P
NetM1_135: M1.135(MIPI_CSI_RX0_D2N) ; port MIPI_CSI_RX0_D2N
NetM1_136: M1.136(MIPI_CSI_RX0_CLK0P) ; port MIPI_CSI_RX0_CLK0P
NetM1_137: M1.137(MIPI_CSI_RX0_CLK0N) ; port MIPI_CSI_RX0_CLK0N
NetM1_138: M1.138(MIPI_CSI_RX0_D1P) ; port MIPI_CSI_RX0_D1P
NetM1_139: M1.139(MIPI_CSI_RX0_D1N) ; port MIPI_CSI_RX0_D1N
NetM1_140: M1.140(MIPI_CSI_RX0_D0P) ; port MIPI_CSI_RX0_D0P
NetM1_141: M1.141(MIPI_CSI_RX0_D0N) ; port MIPI_CSI_RX0_D0N
NetM1_154: M1.154(I2C1_SDA_M0/GPIO0_B4_d) ; port LCD_PWREN_H_GPIO0_B4_d
NetM1_157: M1.157(SPDIF_TX_M1/CPU_AVS/PWM4_M0/SPI0_CSN1_M0/GPIO0_B7_d) ; port LCD_BL_PWM_GPIO0_B7_d
NetM1_158: M1.158(GPU_AVS/PWM7_M0/UART2_TX_M0/CAN1_TX_M1/GPIO0_C0_d) ; port USB_OTG_DET_GPIO0_C0_d
NetM1_159: M1.159(SPI0_CSN0_M0/PWM5_M0/UART2_CTSN_M0/GPIO0_C2_d) ; port SPI0_CSN0_M0
NetM1_160: M1.160(SPI0_CLK_M0/PWM0_M0/UART2_RTSN_M0/GPIO0_C3_d) ; port SPI0_CLK_M0
NetM1_161: M1.161(SPI0_MOSI_M0/PWM1_M0/UART6_CTSN_M0/GPIO0_C4_d) ; port SPI0_MOSI_M0
NetM1_162: M1.162(SPI0_MISO_M0/PWM2_M0/UART6_RTSN_M0/GPIO0_C5_d) ; port SPI0_MISO_M0
NetM1_163: M1.163(UART6_TX_M0/CAN0_TX_M2/GPIO0_C6_d) ; port UART6_TX_M0
NetM1_164: M1.164(UART6_RX_M0/CAN0_RX_M2/GPIO0_C7_d) ; port UART6_RX_M0
NetM1_165: M1.165(JTAG_CPU_MCU_TMS_M0/UART0_RX_M0/GPIO0_D0_u) ; port UART0_RX_M0_DEBUG
NetM1_166: M1.166(JTAG_CPU_MCU_TCK_M0/UART0_TX_M0/GPIO0_D1_u) ; port UART0_TX_M0_DEBUG
NetM1_167: M1.167(PCIE20_BUTTONRSTN/CLK0_32K_OUT/CLK_32K_IN/GPIO0_B0_d) ; port BT_REG_ON_H_GPIO0_B0_d
NetM1_168: M1.168(PWM3_M0/GPIO0_A7_d) R1173.2 ; port HOST_WAKE_BT_H_GPIO0_A7_d
NetM1_169: M1.169(PCIE20_CLKREQN_M0/GPIO0_A6_d) ; port GMAC1_RSTn_GPIO0_A6_d
NetM1_170: M1.170(PMU_DEBUG/I2C4_SCL_M1/SDMMC0_PWREN/GPIO0_A5_d) ; port GPIO0_A5_d
NetM1_171: M1.171(I2C4_SDA_M1/SDMMC0_DETN/GPIO0_A4_u) ; port SDMMC0_DET_L
NetM1_172: M1.172(REF_CLK_OUT/GPIO0_A0_d) ; port WIFI_REG_ON_H_GPIO0_A0_d
NetM1_174: M1.174(SPKP_OUT) TP4.1 ; port SPKP_OUT
NetM1_175: M1.175(SPKN_OUT) TP5.1 ; port SPKN_OUT
NetM1_176: M1.176(BATDIV) TP3.1 ; port BATDIV
NetM1_177: M1.177(SNSP) TP2.1 ; port SNSP
NetM1_178: M1.178(SNSN) TP1.1 ; port SNSN
NetM1_179: M1.179(SARADC0_BOOT) R1202.1 ; port SARADC0_BOOT
NetQ1_1: Q1.1(GATE) R21.2
NetR21_1: R21.1 R415.2 R1173.1 ; port SYS_LED_H
NetR352_1: R429.1 ; port USB_OTG_PWREN

Not connected (* = marked no-connect by the designer): LED1 3(E)*

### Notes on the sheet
- VDC
- (near R19) LED
- TF_CARD

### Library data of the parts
C269-C271 = C-0402_Dup1: as C29 on sheet P11
C272-C277 = C-0402_Dup1: Part Number: C020102120054; Part Name: 贴片电容; Manufacture: 三星¦国巨¦村田; PCB Footprint: C0402; ERP Number: 1010200084; DSC1: ±10%; DSC3: X7R; ID: 54
C278 = C-0603: as C1011 on sheet P11
C279 = C-0402_Dup1: Manufacture: 三星¦国巨¦村田; Part Name: 贴片电容; Part Number: C020102120018; PCB Footprint: C0402; ID: 18; DSC3: C0G; DSC1: ±0.25PF; ERP Number: 1010200056
C282 C283 = C-0603: Manufacture: 三星¦国巨¦村田; Part Name: 贴片电容; Part Number: C020107143899; PCB Footprint: C0603; ID: 83; DSC3: X5R; DSC1: ±20%
C287 = C-0402_Dup2: as C30 on sheet P11
C302 C1049 C1050 = C-0402_Dup2: as C871 on sheet P11
D79 = DI-TVS-D: ESD 0402; Manufacturer: INPAQ; Manufacture P/N: MLVG04021R0UV18; Part Number: EB3.1R0UV18402A; Part Name: TVS; Manufacture: 硕凯; PN Type: Varistor; DSC1: 双向; DSC2: Vrwm=6.0V; DSC3: VBR=6.67V; DSC4: Vc=10.3V; DSC5: Ipp=58.3A; DSC6: Ppp=200W; ID: 26
Hole5 = MH-NOE: Part Number: CAD; Part Name: 镀锡(金)焊盘固定孔; DSC1: 顶层和底层焊盘直径=6mm; DSC3: 8个过孔; ID: 33
Hole9-Hole11 = MH-NOE_Dup1: Part Number: CAD; Part Name: 镀锡(金)焊盘固定孔; DSC1: 顶层和底层焊盘直径=6mm; DSC2: 孔径3.7mm; DSC3: 8个过孔; ID: 33
J2-J5 J48-J51 = J-H-3P: Part Name: PH; ID: 12
J6 = J-TF-01A: Part Name: SD卡座; Part Number: J080102980002; ID: 2; DSC5: XKTF-N02-N(星坤); DSC4: KLM-1007（九龙熹）; DSC3: 贴片; DSC1: 自弹式 MicroSD卡(TF卡) 卡座 外焊 外扣,无弹片 本体最大高度：2mm
LED1 = D-LED-CT: Part Number: C140202660007; DSC1: 黄色LED，侧贴，3.2*1.5*1.0mm Right Angle SMD VF=2V; DSC2: E6C1204UYAC1UDA(亿晶源); ID: 11
M1 = SOM3562_3
Q1 = N-MOS-Q: as Q7 on sheet P11
R11-R14 = R-0402_Dup3: Part Number: C011002080778; Part Name: 贴片电阻; ID: 778; DSC2: 1/16W; DSC1: ±1%
R15 R16 = R-0402_Dup3: Part Name: 贴片电阻; Part Number: C011002080778; DSC1: ±1%; DSC2: 1/16W; ID: 778
R17 = R-0402_Dup3: as R4 on sheet P11
R19 R21 = R-0402_Dup3: as R9 on sheet P11
R25 = R-0402_Dup3: Part Name: 贴片电阻; Part Number: C011002080262; ERP Number: 1010200173; DSC1: ±5%; DSC2: 1/16W; ID: 262
R28 = R-0402_Dup3: Part Number: C011002080279; Part Name: 贴片电阻; ID: 279; DSC2: 1/16W; DSC1: ±5%; ERP Number: 1010200160
R78 = R-0402_Dup3: Part Name: 贴片电阻; Part Number: C011002080303; ERP Number: 1010200104; DSC1: ±5%; DSC2: 1/16W; ID: 303
R382-R384 = R-0402_Dup3: Part Name: 贴片电阻; Part Number: C011002080413; DSC1: ±1%; DSC2: 1/16W; ID: 413
R389 = R-0402_Dup3: Part Number: C011002080345; Part Name: 贴片电阻; ID: 345; DSC2: 1/16W; DSC1: ±5%; ERP Number: 1010200182
R391 = R-0402_Dup3: as R10 on sheet P11
R415 R431 = R-0402_Dup3: as R1062 on sheet P11
R429 = R-0402_Dup3: Part Number: C011002080217; Part Name: 贴片电阻; ID: 217; DSC2: 1/16W; DSC1: ±5%; ERP Number: 1010200100
R430 R1082 R1173 = R-0402_Dup3: Part Name: 贴片电阻; Part Number: C011002080217; ERP Number: 1010200100; DSC1: ±5%; DSC2: 1/16W; ID: 217
R1202 R1209 R1210 = R-0603_Dup1: as R1084 on sheet P11
TP1 TP3 TP4 = TP-TEST: Part Number: CAD; Part Name: 测试点; ID: 3; DSC4: 单面; DSC3: 圆形; DSC2: 无孔; DSC1: 焊盘1mm
TP2 TP5 = TP-TEST: Part Number: CAD; Part Name: 测试点; DSC1: 焊盘1mm; DSC2: 无孔; DSC3: 圆形; DSC4: 单面; ID: 3

## Sheet P13.SchDoc
size 420 x 297 mm
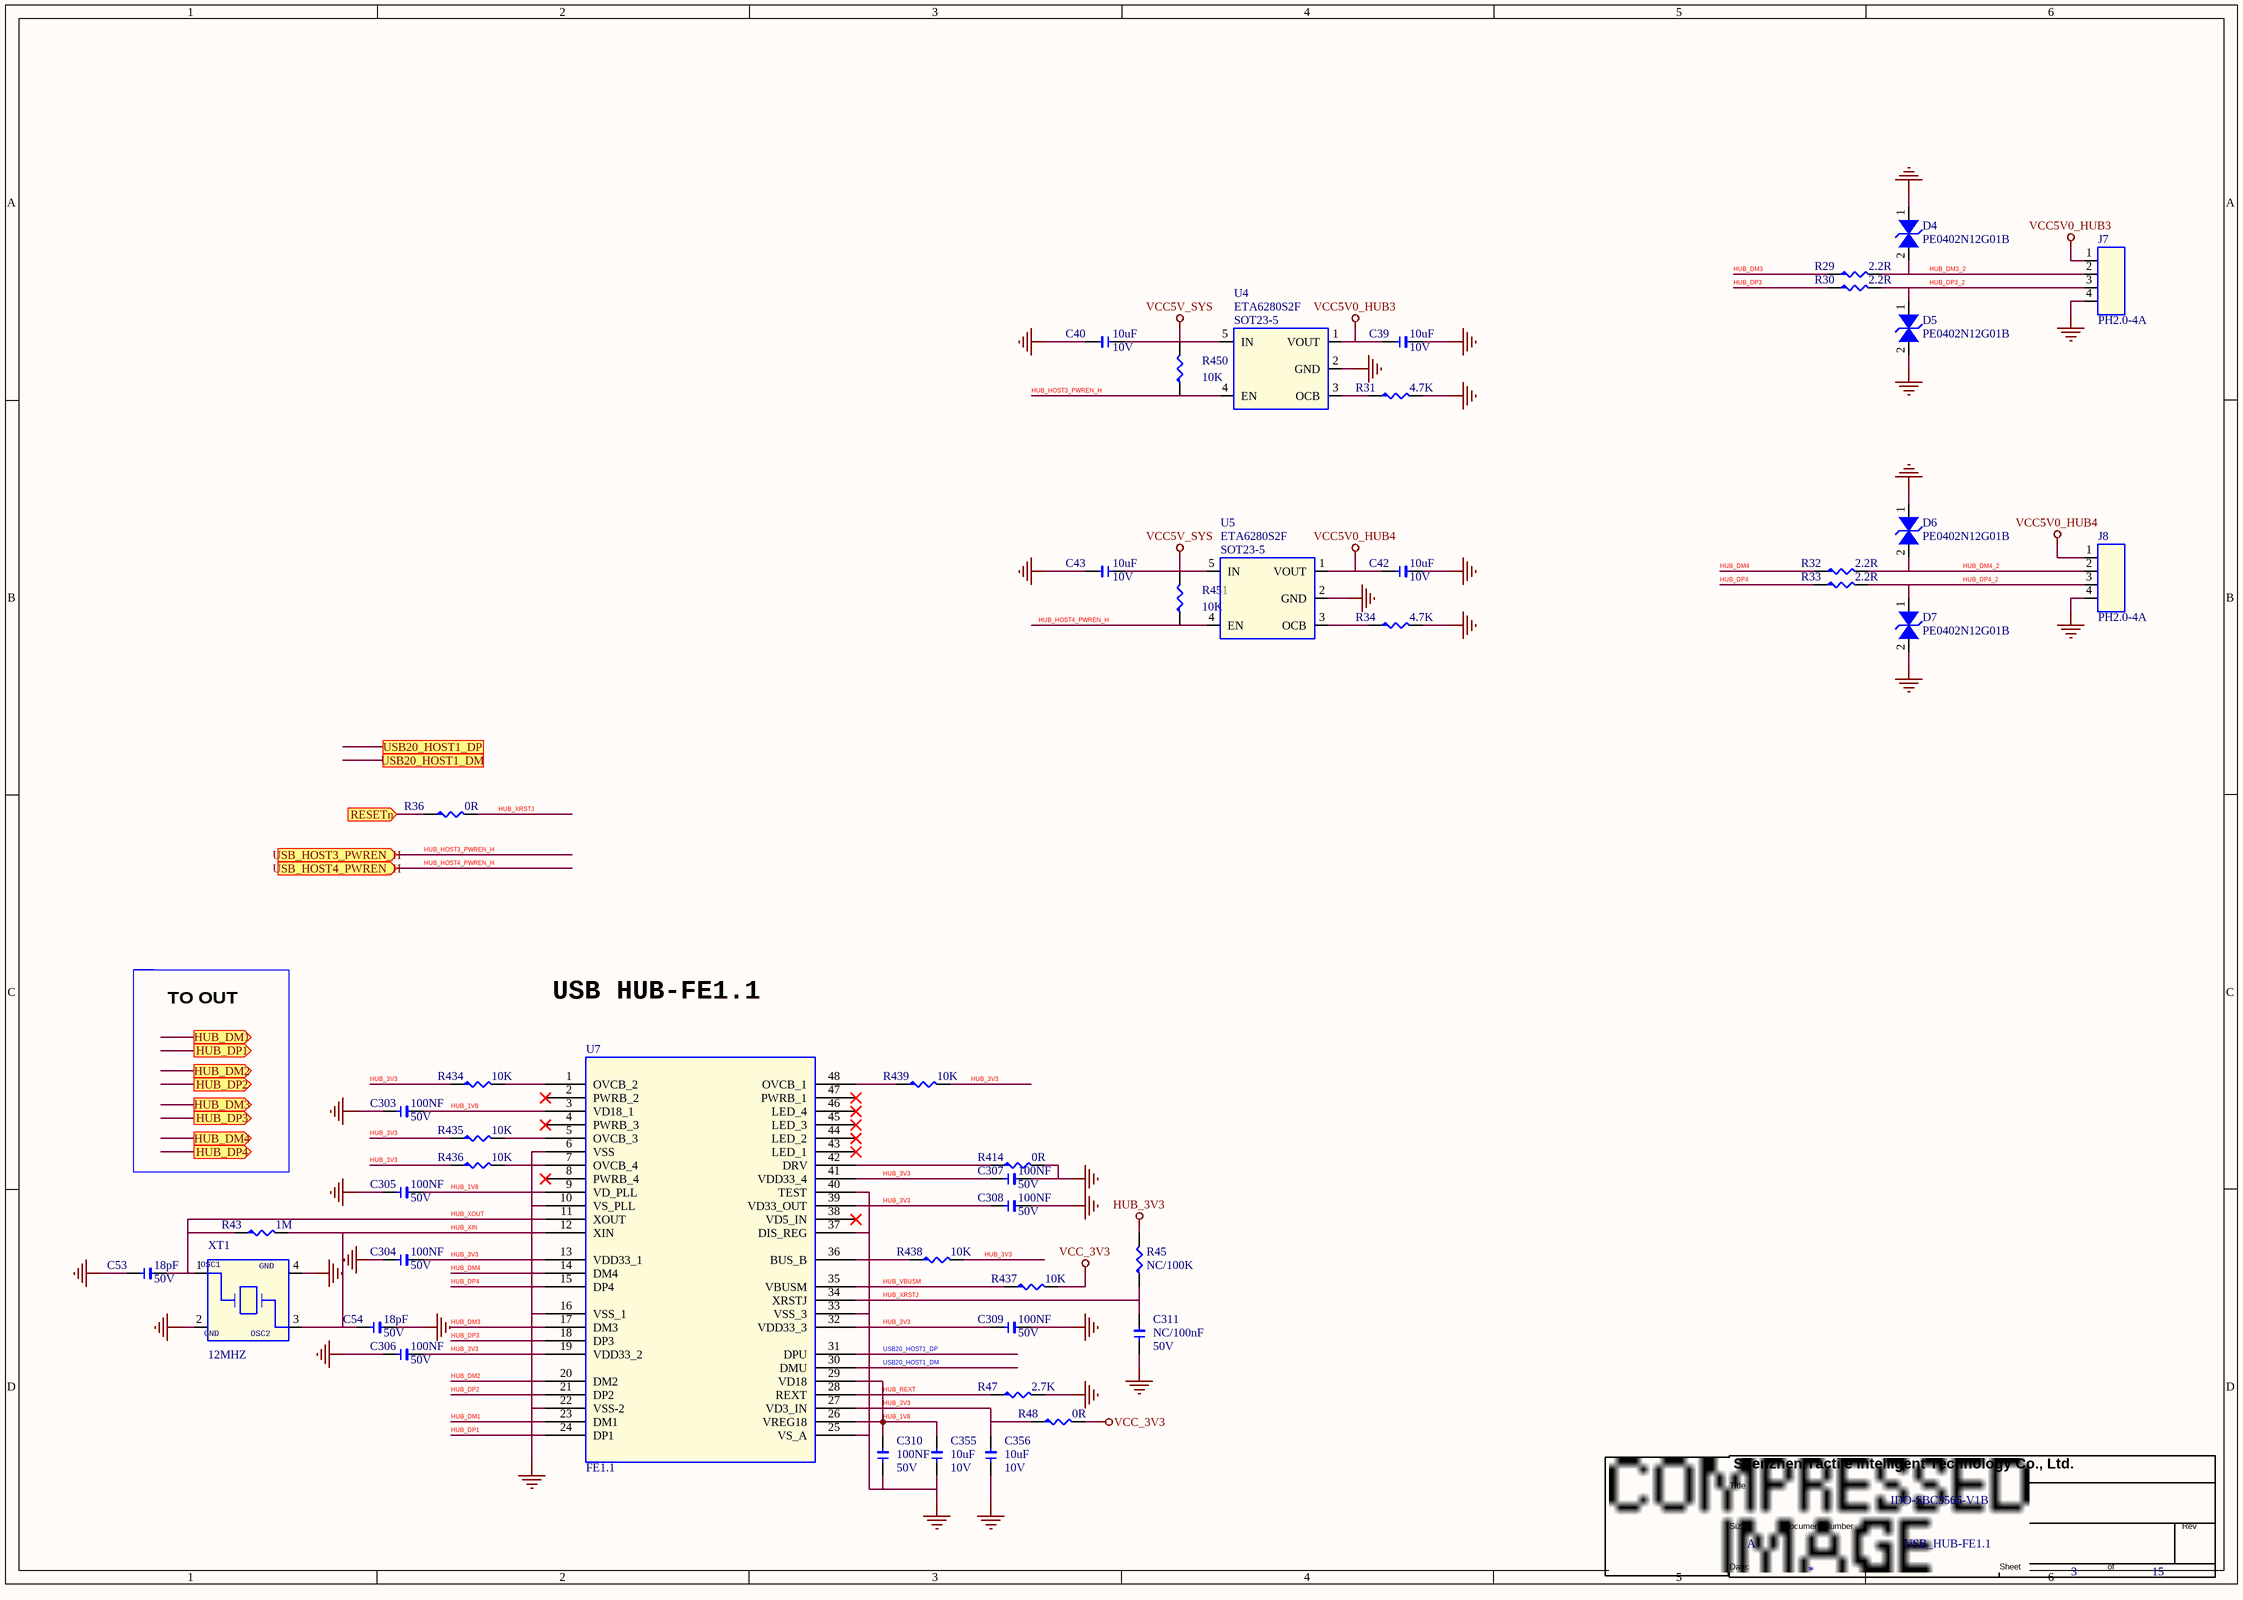
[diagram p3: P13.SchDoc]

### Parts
(Parts that share a designator on the sheet are numbered #1, #2 ... from top to bottom, then left to right.)
*#1  Page Count: 15  Page Number: 3  Page Size: A  Title: IDO-SBC3566-V1B  Doc: USB_HUB-FE1.1  (hidden comment: TitleBlock1)  (graphical)
C39  10uF  DSC2: 10V  [1206]
C40  10uF  DSC2: 10V  [1206]
C42  10uF  DSC2: 10V  [1206]
C43  10uF  DSC2: 10V  [1206]
C53  18pF  DSC2: 50V  [1206]
C54  18pF  DSC2: 50V  [1206]
C303  100NF  DSC2: 50V  [1206]
C304  100NF  DSC2: 50V  [1206]
C305  100NF  DSC2: 50V  [1206]
C306  100NF  DSC2: 50V  [1206]
C307  100NF  DSC2: 50V  [1206]
C308  100NF  DSC2: 50V  [1206]
C309  100NF  DSC2: 50V  [1206]
C310  100NF  DSC2: 50V  [1206]
C311  NC/100nF  DSC2: 50V  [1206]
C355  10uF  DSC2: 10V  [1206]
C356  10uF  DSC2: 10V  [1206]
D4  PE0402N12G01B  [V0402]
D5  PE0402N12G01B  [V0402]
D6  PE0402N12G01B  [V0402]
D7  PE0402N12G01B  [V0402]
J7  PH2.0-4A  [PH200-4A]
J8  PH2.0-4A  [PH200-4A]
R29  2.2R  [R0402]
R30  2.2R  [R0402]
R31  4.7K  [R0402]
R32  2.2R  [R0402]
R33  2.2R  [R0402]
R34  4.7K  [R0402]
R36  0R  [R0402]
R43  1M  [R0402]
R45  NC/100K  [R0402]
R47  2.7K  [R0402]
R48  0R  [R0402]
R414  0R  [R0402]
R434  10K  [R0402]
R435  10K  [R0402]
R436  10K  [R0402]
R437  10K  [R0402]
R438  10K  [R0402]
R439  10K  [R0402]
R450  10K  [R0402]
R451  10K  [R0402]
U4  ETA6280S2F  [SOT23-5]
U5  ETA6280S2F  [SOT23-5]
U7  FE1.1  [LQFP-48_7x7x05P]
XT1  12MHZ  [xtal_32x25_4p]

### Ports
HUB_DM1 (out), HUB_DM2 (out), HUB_DM3 (out), HUB_DM4 (out), HUB_DP1 (out), HUB_DP2 (out), HUB_DP3 (out), HUB_DP4 (out), RESETn (in), USB20_HOST1_DM, USB20_HOST1_DP, USB_HOST3_PWREN_H (in), USB_HOST4_PWREN_H (in)

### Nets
GND: C39.2 C40.2 C42.2 C43.2 C53.1 C54.2 C303.1 C304.1 C305.1 C306.1 C307.2 C308.2 C309.2 C310.1 C311.1 C355.1 C356.1 D4.1(I/O2) D5.2(I/O1) D6.1(I/O2) D7.2(I/O1) J7.4 J8.4 R31.2 R34.2 R47.2 R414.2 U4.2(GND) U5.2(GND) U7.6(VSS) U7.10(VS_PLL) U7.16(VSS_1) U7.22(VSS-2) U7.25(VS_A) U7.33(VSS_3) U7.37(DIS_REG) U7.40(TEST) XT1.2 XT1.4
HUB_1V8: C303.2 C304.2 C305.2 C306.2 C307.1 C308.1 C309.1 C310.2 C355.2 C356.2 R45.2 R47.1 R48.1 R434.1 R435.1 R436.1 R438.2 R439.2 U7.3(VD18_1) U7.9(VD_PLL) U7.13(VDD33_1) U7.19(VDD33_2) U7.26(VREG18) U7.27(VD3_IN) U7.28(REXT) U7.29(VD18) U7.32(VDD33_3) U7.39(VD33_OUT) U7.41(VDD33_4)  [also labelled HUB_3V3, HUB_REXT]
VCC5V0_HUB3: C39.1 J7.1 U4.1(VOUT)
VCC5V0_HUB4: C42.1 J8.1 U5.1(VOUT)
VCC5V_SYS: C40.1 C43.1 R450.2 R451.2 U4.5(IN) U5.5(IN)
VCC_3V3: R48.2 R437.2
HUB_DM1: U7.23(DM1)
HUB_DM2: U7.20(DM2)
HUB_DM3: R29.1 U7.17(DM3)
HUB_DM3_2: D4.2(I/O1) J7.2 R29.2
HUB_DM4: R32.1 U7.14(DM4)
HUB_DM4_2: D6.2(I/O1) J8.2 R32.2
HUB_DP1: U7.24(DP1)
HUB_DP2: U7.21(DP2)
HUB_DP3: R30.1 U7.18(DP3)
HUB_DP3_2: D5.1(I/O2) J7.3 R30.2
HUB_DP4: R33.1 U7.15(DP4)
HUB_DP4_2: D7.1(I/O2) J8.3 R33.2
HUB_HOST3_PWREN_H: R450.1 U4.4(EN) ; port USB_HOST3_PWREN_H
HUB_HOST4_PWREN_H: R451.1 U5.4(EN) ; port USB_HOST4_PWREN_H
HUB_VBUSM: R437.1 U7.35(VBUSM)
HUB_XIN: C54.1 R43.2 U7.12(XIN) XT1.3
HUB_XOUT: C53.2 R43.1 U7.11(XOUT) XT1.1
HUB_XRSTJ: C311.2 R36.2 R45.1 U7.34(XRSTJ)
USB20_HOST1_DM: U7.30(DMU)
USB20_HOST1_DP: U7.31(DPU)
NetM1_6: R36.1 ; port RESETn
NetR31_1: R31.1 U4.3(OCB)
NetR34_1: R34.1 U5.3(OCB)
NetR414_1: R414.1 U7.42(DRV)
NetR434_2: R434.2 U7.1(OVCB_2)
NetR435_2: R435.2 U7.5(OVCB_3)
NetR436_2: R436.2 U7.7(OVCB_4)
NetR438_1: R438.1 U7.36(BUS_B)
NetR439_1: R439.1 U7.48(OVCB_1)

Not connected (* = marked no-connect by the designer): U7 2(PWRB_2)* 4(PWRB_3)* 8(PWRB_4)* 38(VD5_IN)* 43(LED_1)* 44(LED_2)* 45(LED_3)* 46(LED_4)* 47(PWRB_1)*

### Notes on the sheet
- TO OUT
- USB HUB-FE1.1

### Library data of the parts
C39 C42 = C-0603: Manufacture: 三星¦国巨¦村田; Part Name: 贴片电容; Part Number: C020102120071; ID: 71; DSC3: X5R; DSC1: ±20%; ERP Number: 1010200076; PCB Footprint: C0603
C40 = C-0603: as C1011 on sheet P11
C43 C355 C356 = C-0603: as C28 on sheet P11
C53 = C-0402_Dup1: Manufacture: 三星¦国巨¦村田; Part Name: 贴片电容; Part Number: C020102120027; ID: 27; DSC3: C0G; DSC1: ±5%; ERP Number: 1010200091; PCB Footprint: C0402
C54 = C-0402_Dup1: Part Number: C020102120027; Part Name: 贴片电容; Manufacture: 三星¦国巨¦村田; ERP Number: 1010200091; DSC1: ±5%; DSC3: C0G; ID: 27; PCB Footprint: C0402
C303-C309 C311 = C-0402_Dup2: Manufacture: 三星¦国巨¦村田; Part Name: 贴片电容; Part Number: C020102120061; PCB Footprint: C0402; ID: 61; DSC3: X7R; DSC1: ±10%; ERP Number: 1010200128
C310 = C-0402_Dup2: as C30 on sheet P11
D4 D5 = DI-ESD: ESD 0402; Part Number: C040504013980; Manufacture P/N: MLVG04021R0UV18; Manufacturer: INPAQ; Manufacture: 硕凯; PN Type: Varistor; Solder: 推荐; ID: 1; DSC5: Cj=0.05pF; DSC4: Vc=40V; DSC2: Vdc=12V; DSC1: 双向
D6 D7 = DI-ESD: ESD 0402; Part Number: C040504013980; Manufacture P/N: MLVG04021R0UV18; Manufacturer: INPAQ; Manufacture: 硕凯; PN Type: Varistor; DSC1: 双向; DSC2: Vdc=12V; DSC4: Vc=40V; DSC5: Cj=0.05pF; ID: 1; Solder: 推荐
J7 J8 = J-H-4P: Part Number: J020302820003; Part Name: PH; DSC1: 4p; DSC2: 2.0mm间距; DSC3: 通孔180度直针; DSC4: 米黄色胶壳 耐高温; DSC5: JLX-PH20-4A（九龙熹）; DSC6: X2016WV-04-46SN(星坤); ID: 13
R29 = R-0402_Dup3: Part Number: C011002080238; Part Name: 贴片电阻; ID: 238; DSC2: 1/16W; DSC1: ±5%; ERP Number: 1010200263
R30 R32 R33 = R-0402_Dup3: Part Name: 贴片电阻; Part Number: C011002080238; ERP Number: 1010200263; DSC1: ±5%; DSC2: 1/16W; ID: 238
R31 = R-0402_Dup3: Part Name: 贴片电阻; Part Number: C011002080320; ERP Number: 1010200177; DSC1: ±5%; DSC2: 1/16W; ID: 320
R34 = R-0402_Dup3: Part Number: C011002080320; Part Name: 贴片电阻; ID: 320; DSC2: 1/16W; DSC1: ±5%; ERP Number: 1010200177
R36 = R-0402_Dup3: as R430 on sheet P12
R43 = R-0402_Dup3: Part Number: C011002080378; Part Name: 贴片电阻; ID: 378; DSC2: 1/16W; DSC1: ±5%; ERP Number: 1010200167
R45 = R-0402_Dup3: as R4 on sheet P11
R47 = R-0402_Dup3: Part Name: 贴片电阻; Part Number: C011002080313; DSC1: ±5%; DSC2: 1/16W; ID: 313
R48 R414 = R-0402_Dup3: as R429 on sheet P12
R434-R439 = R-0402_Dup3: as R1062 on sheet P11
R450 R451 = R-0402_Dup3: as R10 on sheet P11
U4 = U-SY6280AAC: Manufacture: ETA; Part Name: 功率开关; ID: 1; DSC4: -40~85℃; DSC3: 80mA; DSC2: 2.4-5.5V 2A; DSC1: 低能耗电源开关
U5 = U-SY6280AAC: Part Name: 功率开关; Manufacture: ETA; DSC1: 低能耗电源开关; DSC2: 2.4-5.5V 2A; DSC3: 80mA; DSC4: -40~85℃; ID: 1
U7 = U-FE1_1: Manufacture: Terminus; Part Name: USB芯片; Part Number: C100209113928; ID: 48; DSC3: 0℃~+70℃; DSC2: LQFP48,7mm×7mm,0.5mm Pitch; DSC1: USB 2.0 HIGH SPEED 4-PORT HUB CONTROLLER
XT1 = XTAL-4P_1: Part Name: 贴片无源晶振; Part Number: C050102290004; Manufacture: 泰晶; CLASS: IC; ERP Number: 1010700002; DSC1: 100Ω; DSC2: ±10ppm; DSC3: 12pF; DSC4: -40℃~+85℃; DSC5: 3.2*2.5mm 4P; ID: 4

## Sheet P14.SchDoc
size 420 x 297 mm
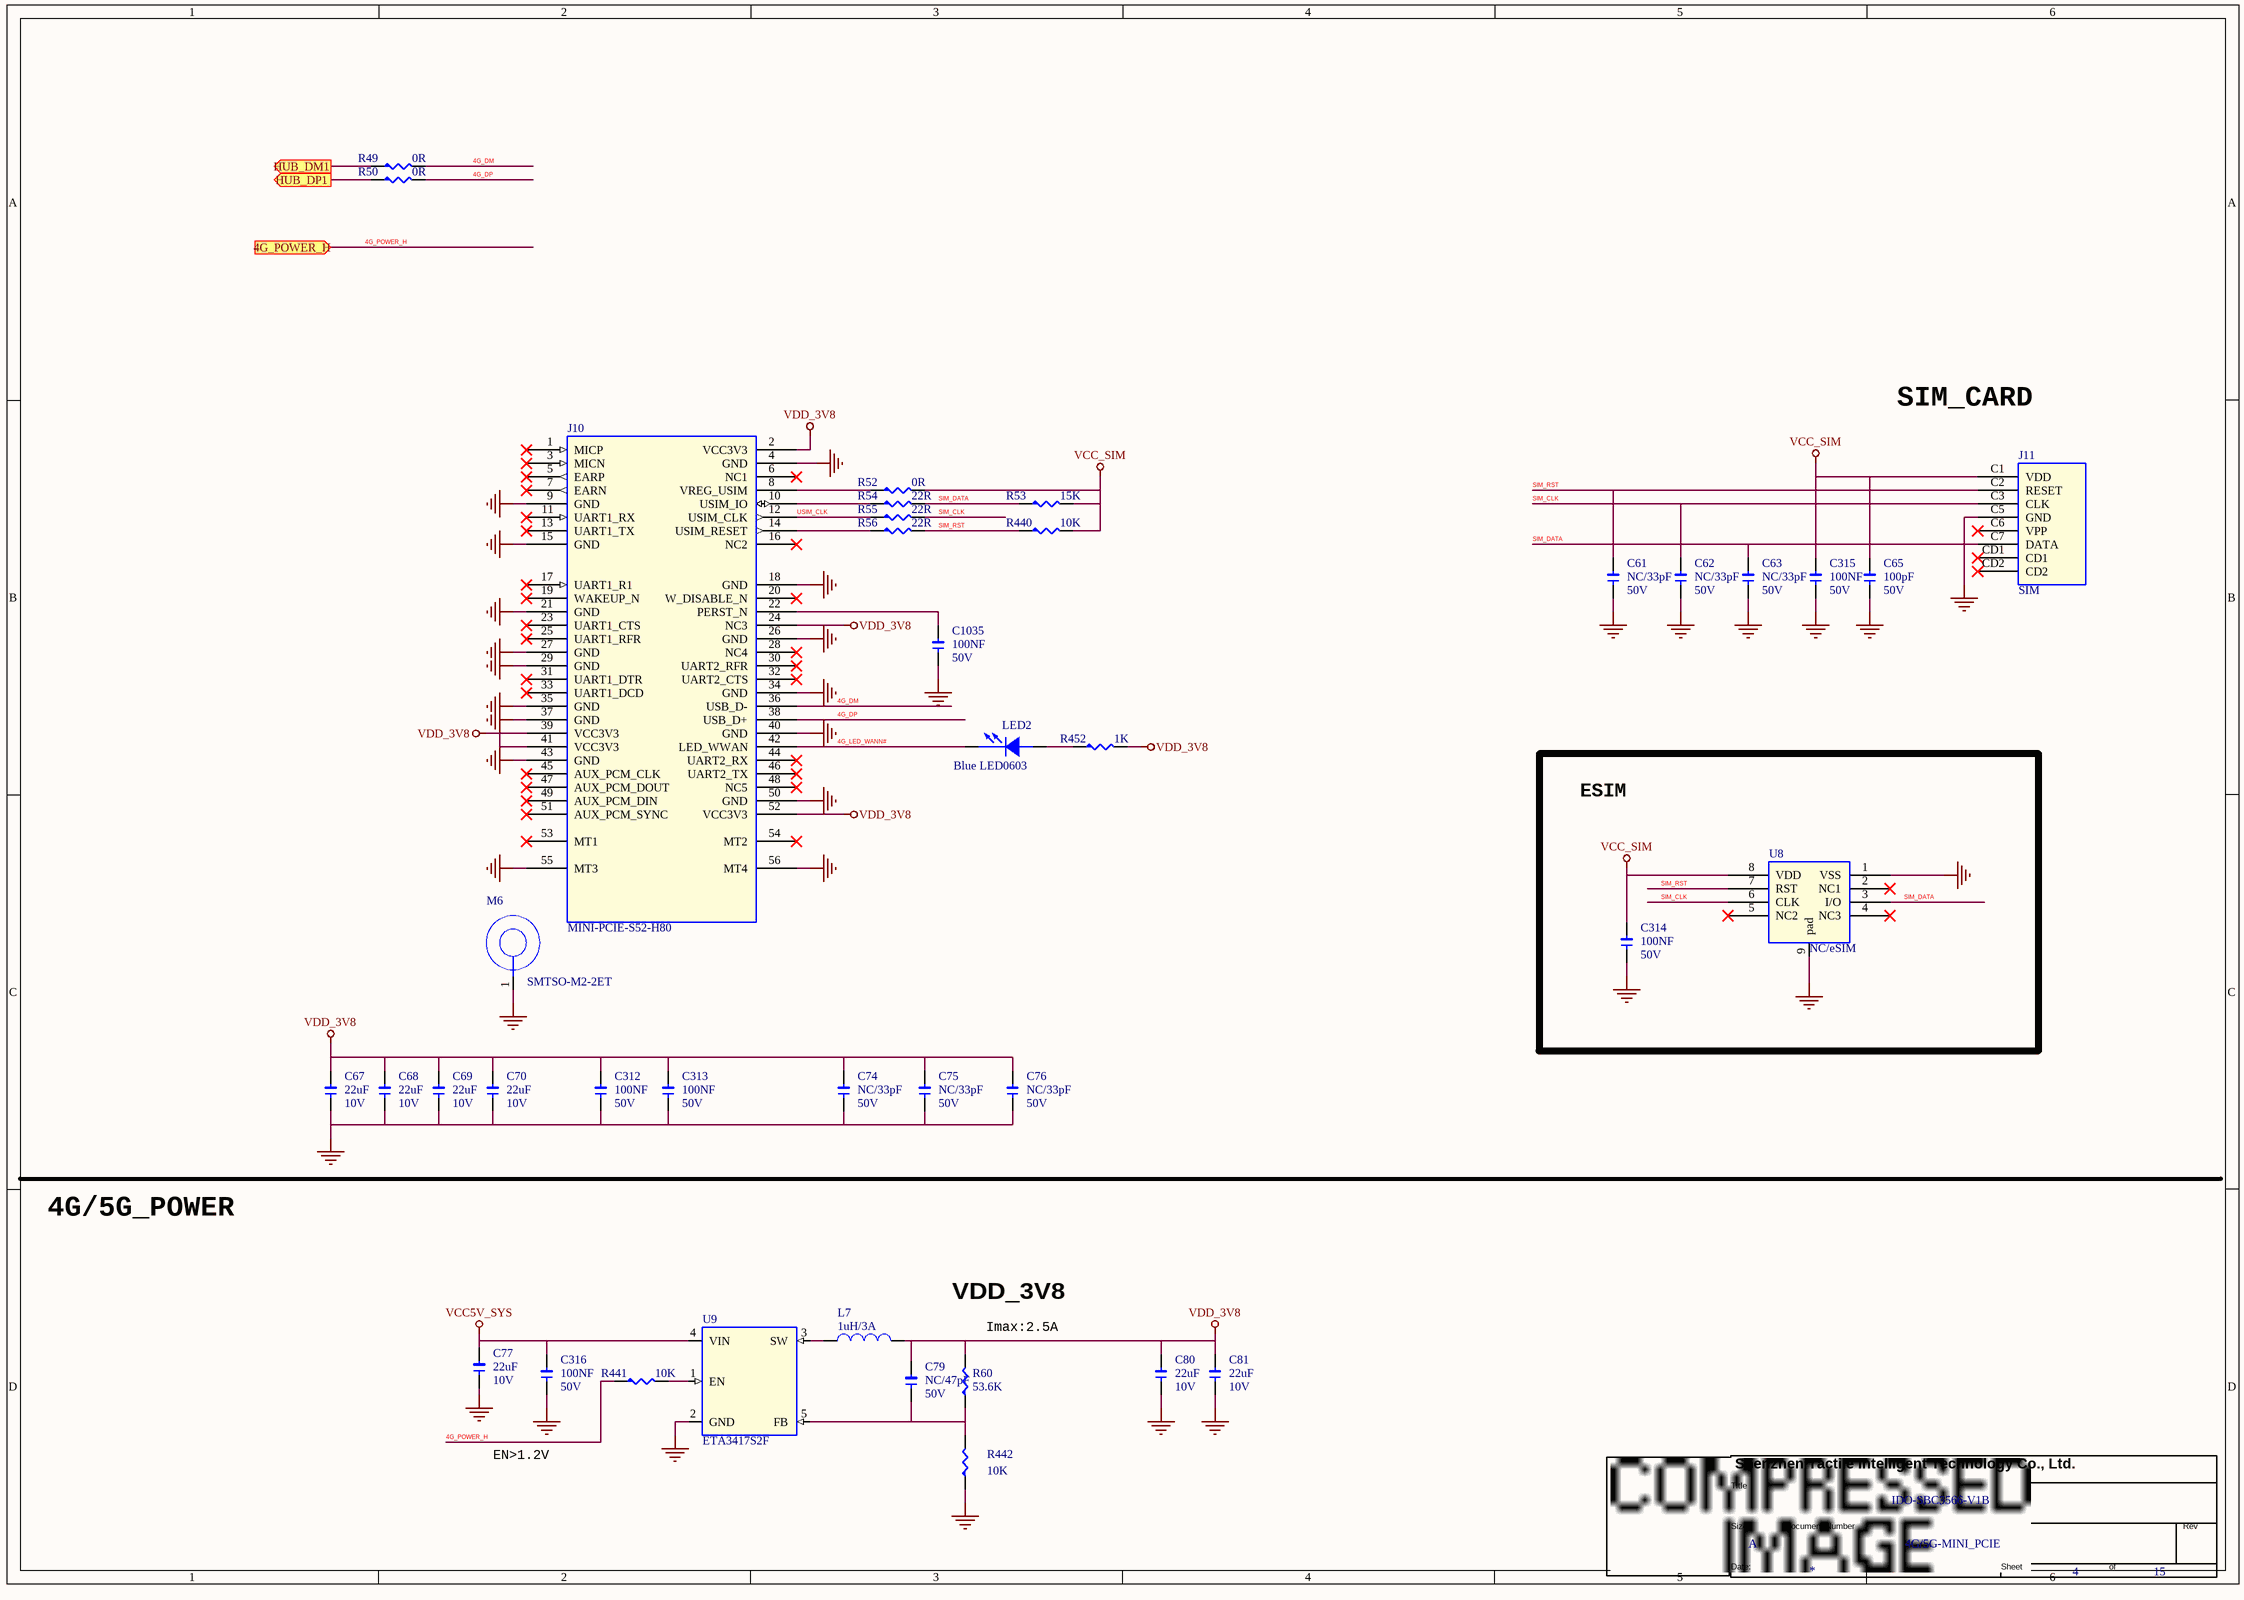
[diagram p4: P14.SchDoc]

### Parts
(Parts that share a designator on the sheet are numbered #1, #2 ... from top to bottom, then left to right.)
*#2  Page Count: 15  Page Number: 4  Page Size: A  Title: IDO-SBC3566-V1B  Doc: 4G/5G-MINI_PCIE  (hidden comment: TitleBlock1)  (graphical)
C61  NC/33pF  DSC2: 50V  [1206]
C62  NC/33pF  DSC2: 50V  [1206]
C63  NC/33pF  DSC2: 50V  [1206]
C65  100pF  DSC2: 50V  [1206]
C67  22uF  DSC2: 10V  [1206]
C68  22uF  DSC2: 10V  [1206]
C69  22uF  DSC2: 10V  [1206]
C70  22uF  DSC2: 10V  [1206]
C74  NC/33pF  DSC2: 50V  [1206]
C75  NC/33pF  DSC2: 50V  [1206]
C76  NC/33pF  DSC2: 50V  [1206]
C77  22uF  DSC2: 10V  [1206]
C79  NC/47pF  DSC2: 50V  [1206]
C80  22uF  DSC2: 10V  [1206]
C81  22uF  DSC2: 10V  [1206]
C312  100NF  DSC2: 50V  [1206]
C313  100NF  DSC2: 50V  [1206]
C314  100NF  DSC2: 50V  [1206]
C315  100NF  DSC2: 50V  [1206]
C316  100NF  DSC2: 50V  [1206]
C1035  100NF  DSC2: 50V  [1206]
J10  MINI-PCIE-S52-H80  [M_MINIPCIE_SOCKET_CK]
J11  SIM  [SIM-91288-021]
L7  1uH/3A  [IND_252012]
LED2  Blue LED0603  [LED0603]
M6  SMTSO-M2-2ET  [MH276_091]
R49  0R  [R0402]
R50  0R  [R0402]
R52  0R  [R0402]
R53  15K  [R0402]
R54  22R  [R0402]
R55  22R  [R0402]
R56  22R  [R0402]
R60  53.6K  [R0402]
R440  10K  [R0402]
R441  10K  [R0402]
R442  10K  [R0402]
R452  1K  [R0402]
U8  NC/eSIM  [eSIM]
U9  ETA3417S2F  [SOT23-5]

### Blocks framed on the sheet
ESIM: C314 U8

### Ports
4G_POWER_H (in), HUB_DM1 (out), HUB_DP1 (out)

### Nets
GND: C61.1 C62.1 C63.1 C65.1 C67.1 C68.1 C69.1 C70.1 C74.1 C75.1 C76.1 C77.1 C80.1 C81.1 C312.1 C313.1 C314.1 C315.1 C316.1 C1035.1 J10.4(GND) J10.9(GND) J10.15(GND) J10.18(GND) J10.21(GND) J10.26(GND) J10.27(GND) J10.29(GND) J10.34(GND) J10.35(GND) J10.37(GND) J10.40(GND) J10.43(GND) J10.50(GND) J10.55(MT3) J10.56(MT4) J11.C5(GND) M6.1 R442.1 U8.1(VSS) U8.9(pad) U9.2(GND)
VCC5V_SYS: C77.2 C316.2 U9.4(VIN)
VCC_SIM: C65.2 C314.2 C315.2 J11.C1(VDD) R52.2 R53.2 R440.2 U8.8(VDD)
VDD_3V8: C67.2 C68.2 C69.2 C70.2 C74.2 C75.2 C76.2 C79.2 C80.2 C81.2 C312.2 C313.2 J10.2(VCC3V3) J10.24(NC3) J10.39(VCC3V3) J10.41(VCC3V3) J10.52(VCC3V3) L7.2 R60.2 R452.2
4G_DM: J10.36(USB_D-) R49.2
4G_DP: J10.38(USB_D+) R50.2
4G_LED_WANN#: J10.42(LED_WWAN) LED2.C(CATHODE)
4G_POWER_H: R441.1 ; port 4G_POWER_H
SIM_CLK: C62.2 J11.C3(CLK) R55.2 U8.6(CLK)
SIM_DATA: C63.2 J11.C7(DATA) R53.1 R54.2 U8.3(I/O)
SIM_RST: C61.2 J11.C2(RESET) R56.2 R440.1 U8.7(RST)
USIM_CLK: J10.12(USIM_CLK) R55.1
NetC79_1: C79.1 R60.1 R442.2 U9.5(FB)
NetC1035_2: C1035.2 J10.22(PERST_N)
NetJ10_8: J10.8(VREG_USIM) R52.1
NetJ10_10: J10.10(USIM_IO) R54.1
NetJ10_14: J10.14(USIM_RESET) R56.1
NetL7_1: L7.1 U9.3(SW)
NetLED2_A: LED2.A(ANODE) R452.1
NetR49_1: R49.1 ; port HUB_DM1
NetR50_1: R50.1 ; port HUB_DP1
NetR441_2: R441.2 U9.1(EN)

Not connected (* = marked no-connect by the designer): J10 1(MICP)* 3(MICN)* 5(EARP)* 6(NC1)* 7(EARN)* 11(UART1_RX)* 13(UART1_TX)* 16(NC2)* 17(UART1_R1)* 19(WAKEUP_N)* 20(W_DISABLE_N)* 23(UART1_CTS)* 25(UART1_RFR)* 28(NC4)* 30(UART2_RFR)* 31(UART1_DTR)* 32(UART2_CTS)* 33(UART1_DCD)* 44(UART2_RX)* 45(AUX_PCM_CLK)* 46(UART2_TX)* 47(AUX_PCM_DOUT)* 48(NC5)* 49(AUX_PCM_DIN)* 51(AUX_PCM_SYNC)* 53(MT1)* 54(MT2)*; J11 C6(VPP)* CD1* CD2*; U8 2(NC1)* 4(NC3)* 5(NC2)*

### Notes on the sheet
- SIM_CARD
- 4G/5G_POWER
- VDD_3V8
- (near R60) Imax:2.5A
- EN>1.2V

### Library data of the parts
C61 C62 C76 = C-0402_Dup1: Part Number: C020102120033; Part Name: 贴片电容; Manufacture: 三星¦国巨¦村田; ERP Number: 1010200087; DSC1: ±5%; DSC3: C0G; ID: 33; PCB Footprint: C0402
C63 C74 C75 = C-0402_Dup1: Manufacture: 三星¦国巨¦村田; Part Name: 贴片电容; Part Number: C020102120033; ID: 33; DSC3: C0G; DSC1: ±5%; ERP Number: 1010200087; PCB Footprint: C0402
C65 = C-0402_Dup1: Manufacture: 三星¦国巨¦村田; Part Name: 贴片电容; Part Number: C020102120040; ID: 40; DSC3: C0G; DSC1: ±5%; ERP Number: 1010200152; PCB Footprint: C0402
C67-C70 C80 C81 = C-0603: as C32 on sheet P11
C77 = C-0603: Manufacture: 三星¦国巨¦村田; Part Name: 贴片电容; Part Number: C020107143899; ID: 83; DSC3: X5R; DSC1: ±20%; PCB Footprint: C0603
C79 = C-0402_Dup1: as C31 on sheet P11
C312-C316 = C-0402_Dup2: as C303 on sheet P13
C1035 = C-0402_Dup2: as C871 on sheet P11
J10 = J-MINIPCIE-52P_0: Part Number: J050102900003; Part Name: 金手指连接器; CLASS: IO; DSC1: miniPCIE座子 H=8.0mm; DSC2: 52P; DSC3: 贴片; DSC4: 91304-80-052R2(UMaxconn); ID: 3
J11 = J-SIM-021: Part Name: SIM卡座; Part Number: J080202990002; ID: 5; DSC5: XKSIM-816-P8(星坤); DSC4: SIM-9036P（九龙熹）; DSC3: 贴片; DSC2: 31.0*25.1*26mm; DSC1: 抽屉式 MiniSIM卡 卡座 8p; ERP Number: 1040100109
L7 = L-IND_Dup1: Part Name: 功率电感; Manufacture: 宗成¦长江微电¦顺络; DSC1: ±20%; DSC2: Isat=3.6A; DSC3: Irms=3A; DSC4: 54mΩ; DSC5: 2.5*2.0*1.2mm; DSC6: WPN252012H1R0MT(顺络); DSC7: FHD252012S-1R0MT(长江微电); DSC8: ZCRH252012-1uH-M(宗成); ID: 52
LED2 = D-LED0603: Part Name: LED; Part Number: C140202660004; ID: 8; DSC3: 19-217/BHC-ZL1M2RY/3T(亿光); DSC2: NCD0603B1(国星光电); DSC1: 蓝色LED，SMD,0603，VF=3V; ERP Number: 1010200068
M6 = MH-NOE_Dup1: Part Number: CAD; ID: 41; DSC1: PCB螺母; PCB Footprint: MTG380_620_SMTSO_M2
R49 R50 R52 = R-0402_Dup3: as R429 on sheet P12
R53 = R-0402_Dup3: Part Number: C011002080332; Part Name: 贴片电阻; ID: 332; DSC2: 1/16W; DSC1: ±5%; ERP Number: 1010200258
R54-R56 = R-0402_Dup3: as R25 on sheet P12
R60 = R-0402_Dup3: Part Name: 贴片电阻; Part Number: C011002080943; DSC1: ±1%; DSC2: 1/16W; ID: 943
R440 R441 = R-0402_Dup3: as R10 on sheet P11
R442 = R-0402_Dup3: as R1062 on sheet P11
R452 = R-0402_Dup3: as R9 on sheet P11
U8 = eSIM
U9 = U-ETA3417S2F: as U3 on sheet P11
